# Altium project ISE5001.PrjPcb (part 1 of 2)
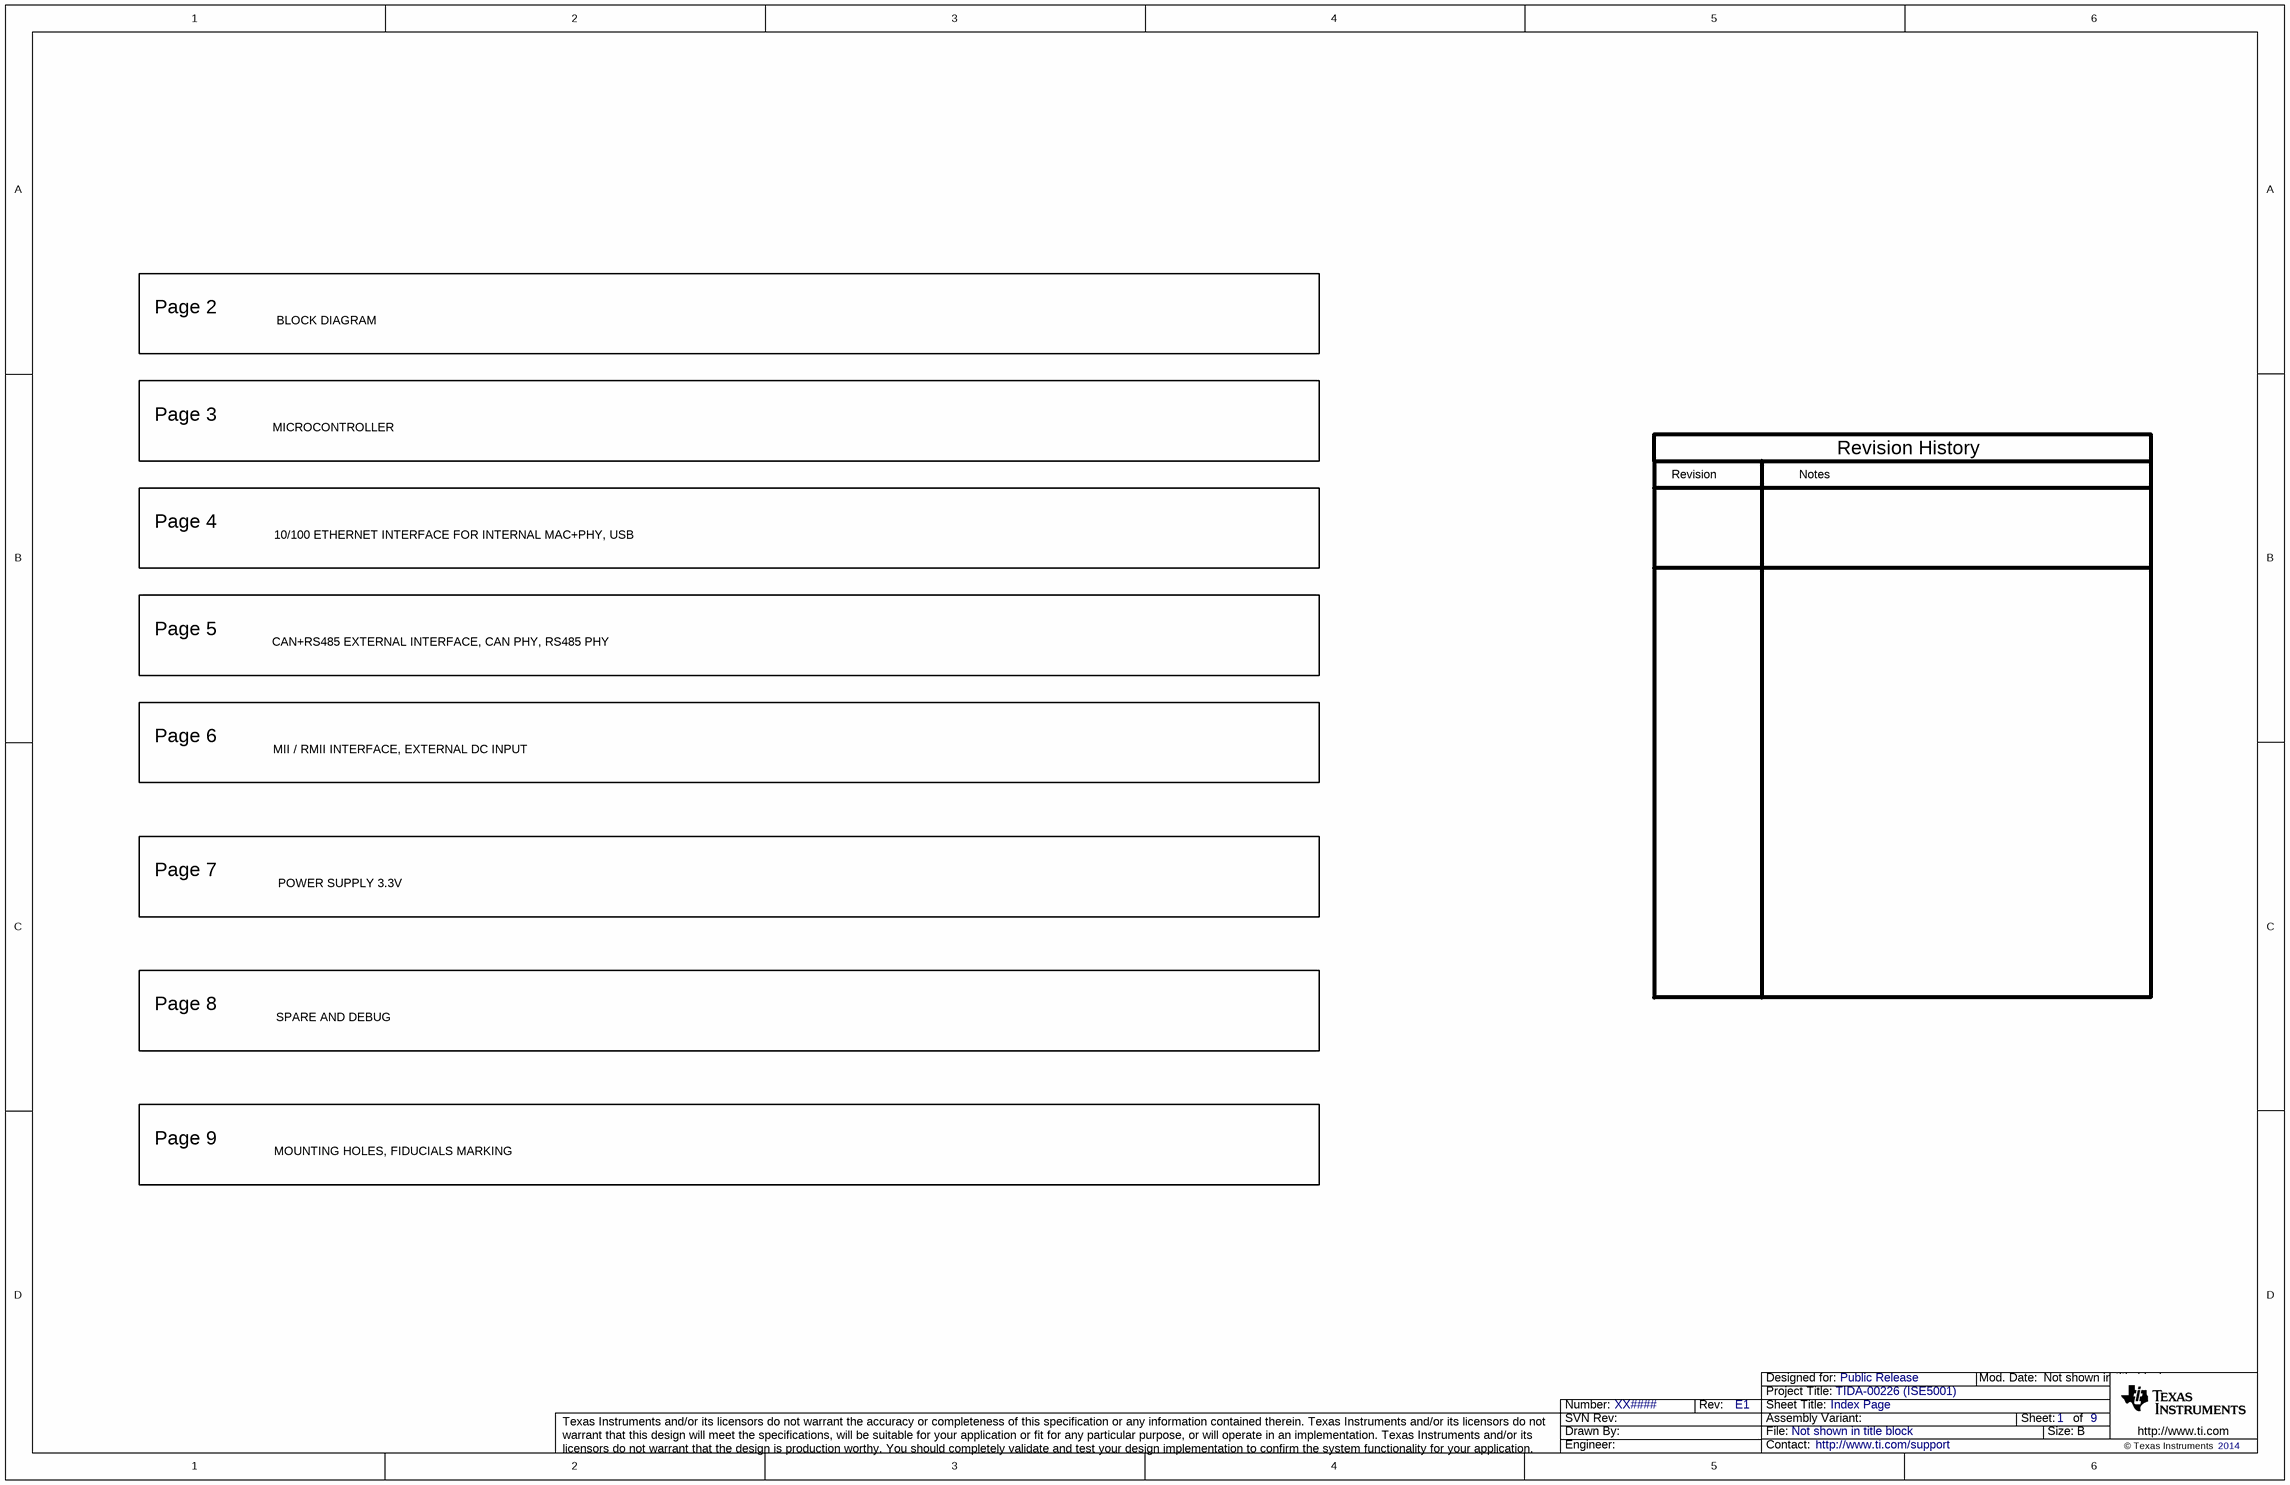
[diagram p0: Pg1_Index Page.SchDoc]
TechSupport: http://www.ti.com/support; SCH_Rev: E1; PRJ_Title: TIDA-00226 (ISE5001); PRJ_Number: XX####; PRJ_Customer: Public Release; CopyrightYear: 2014
9 sheets, 189 parts. Net scope: flat (ports and power ports of the same name join across sheets).
Board file: ISE5001.PcbDoc
Sheets:
  Pg1_Index Page.SchDoc
  Pg2_Block_Diagram.SchDoc
  Pg3_MICROCONTROLLER.SchDoc
  Pg4_10_100_ETHERNET_USB.SchDoc
  Pg5_CAN_RS485.SchDoc
  Pg6_MII_RMII_INTERFACE.SchDoc
  Pg7_POWER_SUPPLY.SchDoc
  Pg8_SPARE_AND_DEBUG.SchDoc
  Pg9_Hardware_ANSI-B.SchDoc

## Sheet Pg1_Index Page.SchDoc: Index Page
size 431 x 279 mm; Date: Not shown in title block; ApprovedBy: Not shown in title block; CheckedBy: Not shown in title block; Author: Not shown in title block; CompanyName: Not shown in title block; Engineer: Not shown in title block; Organization: Not shown in title block; Address1: Not shown in title block; Address2: Not shown in title block; Address3: Not shown in title block; Address4: Not shown in title block; DocumentNumber: 1; Revision: Use project parameter SCH_Rev; SheetNumber: 1; SheetTotal: 9; PageSetup: Record=PageOptions|CenterHorizontal=True|CenterVertical=True|PrintScale=1.00|XCorrection=1.00|YCorrection=1.00|PrintKind=0|BorderSize=5000000|LeftOffset=0|BottomOffset=0|Orientation=2|PaperLength=1000|PaperWidth=1000|Scale=100|PaperSource=15|PrintQuality=600|MediaType=1|DitherType=10|PaperKind=Letter|PrintScaleMode=1

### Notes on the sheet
- Page 2
- BLOCK DIAGRAM
- Page 3
- MICROCONTROLLER
- Revision
- Notes
- Revision History
- Page 4
- 10/100 ETHERNET INTERFACE FOR INTERNAL MAC+PHY, USB
- Page 5
- CAN+RS485 EXTERNAL INTERFACE, CAN PHY, RS485 PHY
- Page 6
- MII / RMII INTERFACE, EXTERNAL DC INPUT
- Page 7
- POWER SUPPLY 3.3V
- Page 8
- SPARE AND DEBUG
- Page 9
- MOUNTING HOLES, FIDUCIALS MARKING

## Sheet Pg2_Block_Diagram.SchDoc: BLOCK DIAGRAM
size 431 x 279 mm; Date: Not shown in title block; ApprovedBy: Not shown in title block; CheckedBy: Not shown in title block; Author: Not shown in title block; CompanyName: Not shown in title block; Engineer: Not shown in title block; Organization: Not shown in title block; Address1: Not shown in title block; Address2: Not shown in title block; Address3: Not shown in title block; Address4: Not shown in title block; DocumentNumber: 2; Revision: Use project parameter SCH_Rev; SheetNumber: 2; SheetTotal: 9; PageSetup: Record=PageOptions|CenterHorizontal=True|CenterVertical=True|PrintScale=1.00|XCorrection=1.00|YCorrection=1.00|PrintKind=0|BorderSize=5000000|LeftOffset=0|BottomOffset=0|Orientation=2|PaperLength=1000|PaperWidth=1000|Scale=100|PaperSource=15|PrintQuality=600|MediaType=1|DitherType=10|PaperKind=Letter|PrintScaleMode=1
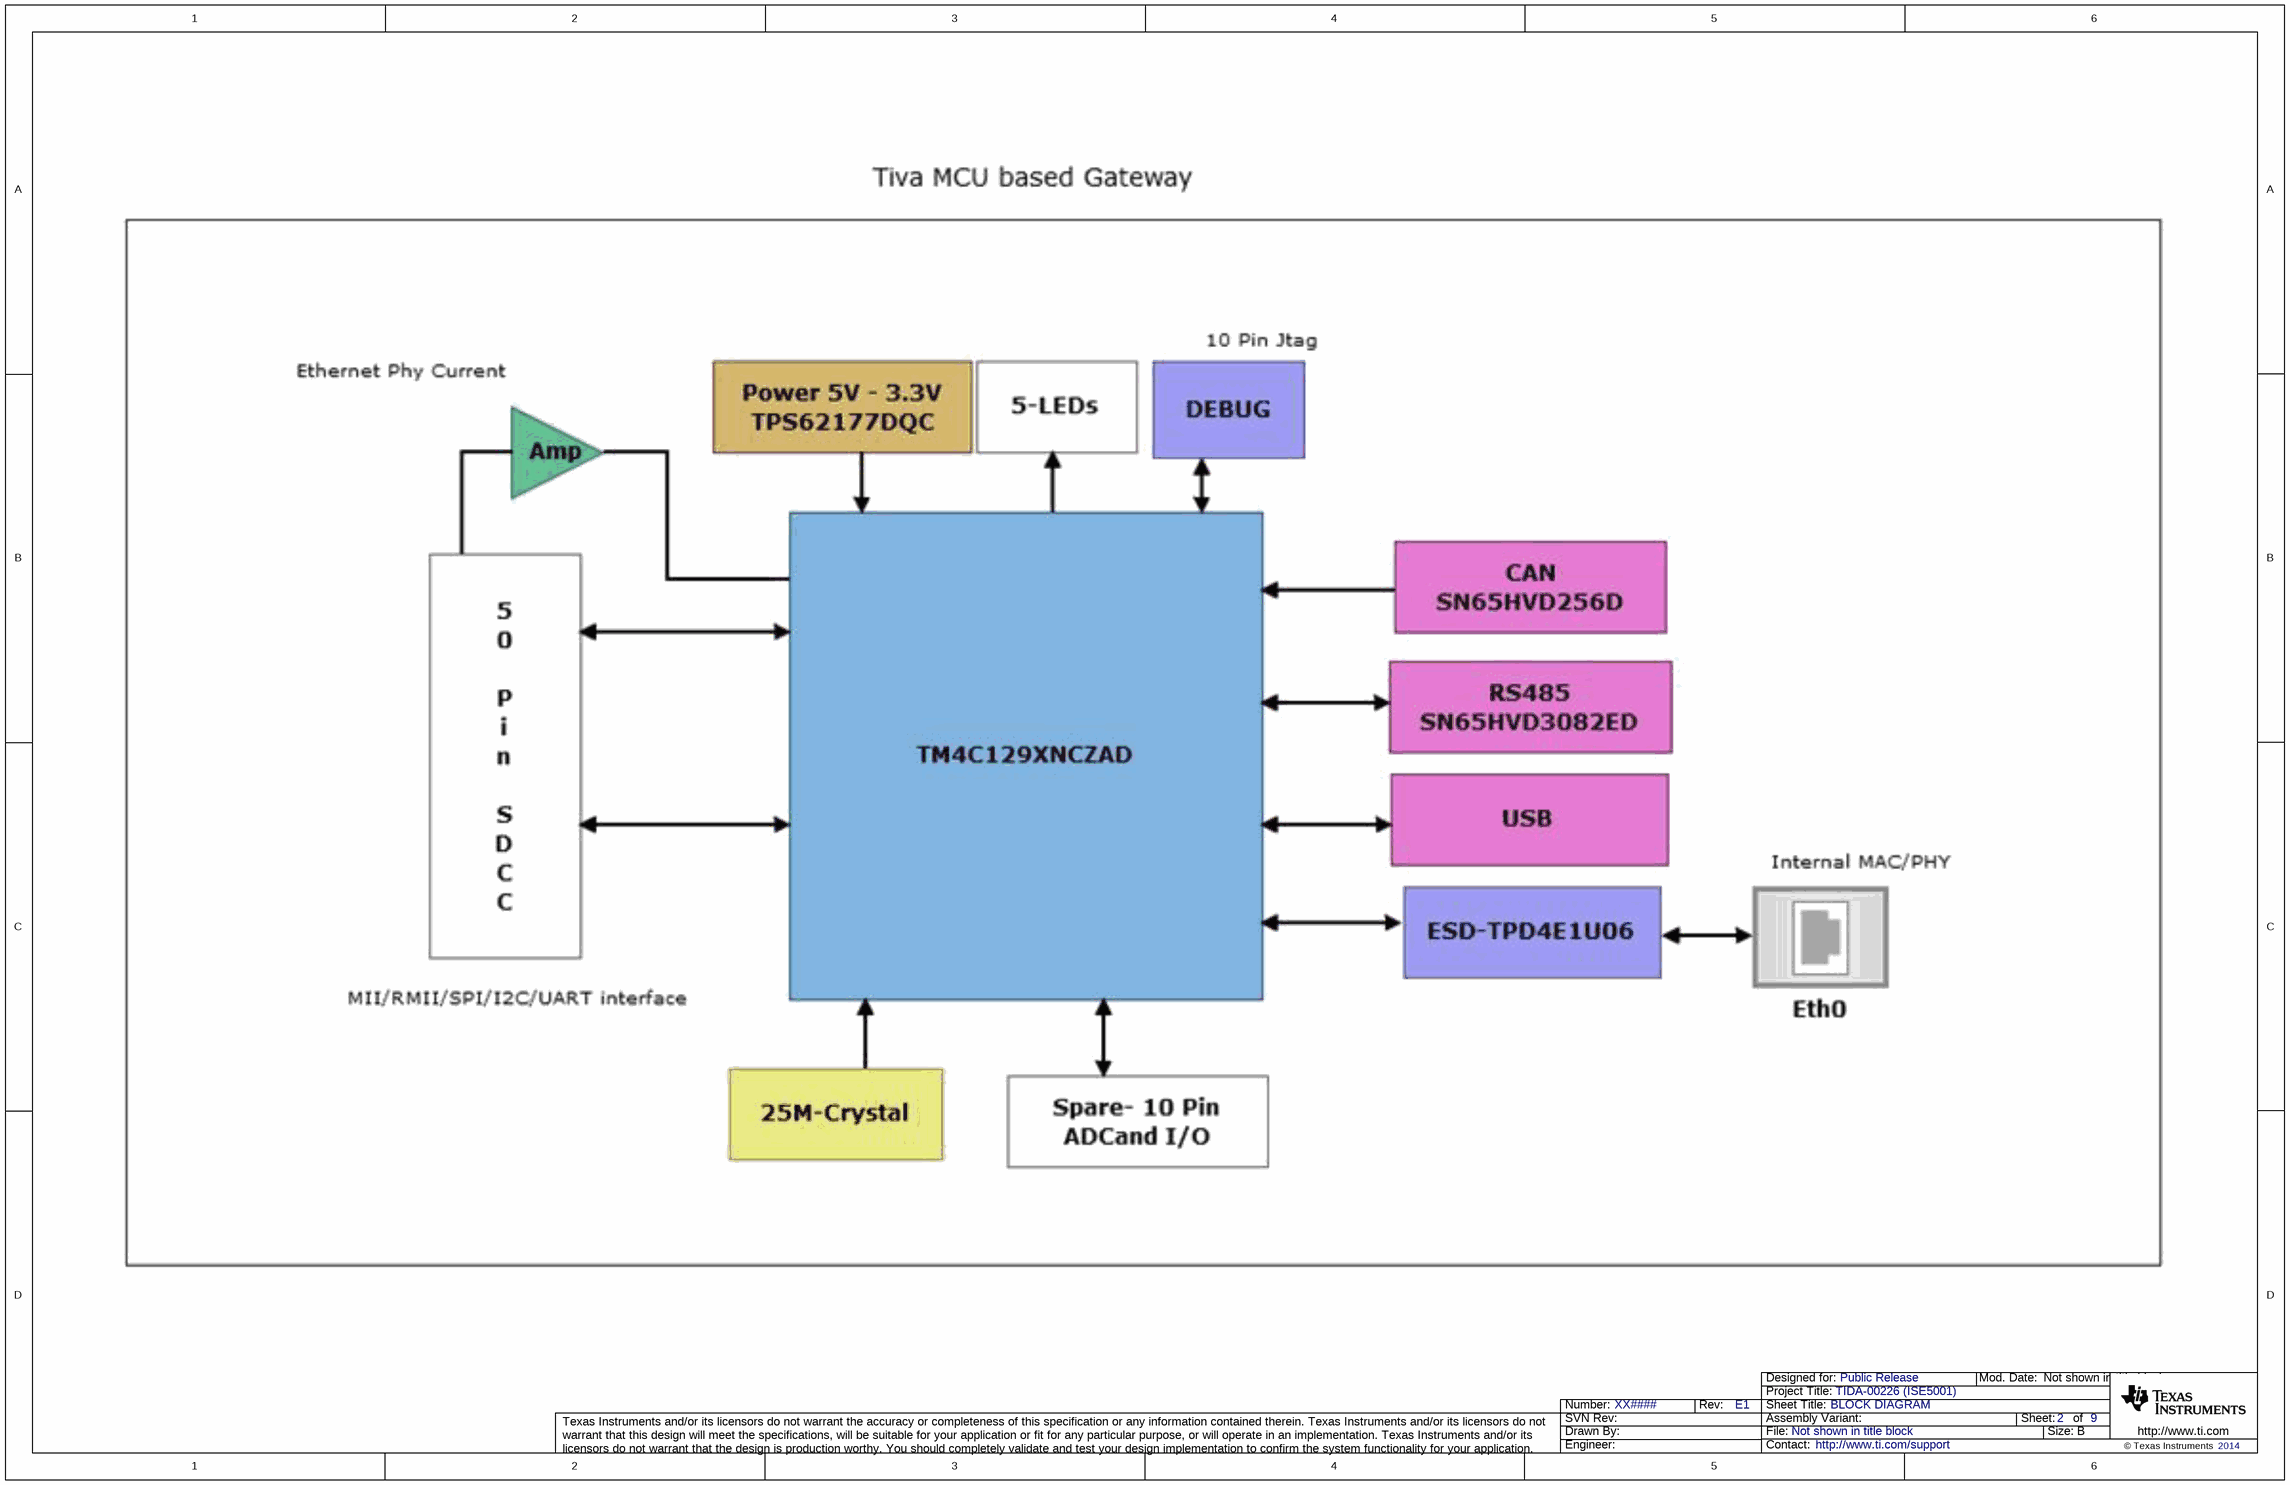
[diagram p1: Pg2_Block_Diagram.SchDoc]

## Sheet Pg3_MICROCONTROLLER.SchDoc: MICROCONTROLLER
size 431 x 279 mm; Date: Not shown in title block; ApprovedBy: Not shown in title block; CheckedBy: Not shown in title block; Author: Not shown in title block; CompanyName: Not shown in title block; Engineer: Not shown in title block; Organization: Not shown in title block; Address1: Not shown in title block; Address2: Not shown in title block; Address3: Not shown in title block; Address4: Not shown in title block; DocumentNumber: 3; Revision: Use project parameter SCH_Rev; SheetNumber: 3; SheetTotal: 9; PageSetup: Record=PageOptions|CenterHorizontal=True|CenterVertical=True|PrintScale=1.00|XCorrection=1.00|YCorrection=1.00|PrintKind=0|BorderSize=5000000|LeftOffset=0|BottomOffset=0|Orientation=2|PaperLength=1000|PaperWidth=1000|Scale=100|PaperSource=15|PrintQuality=600|MediaType=1|DitherType=10|PaperKind=Letter|PrintScaleMode=1
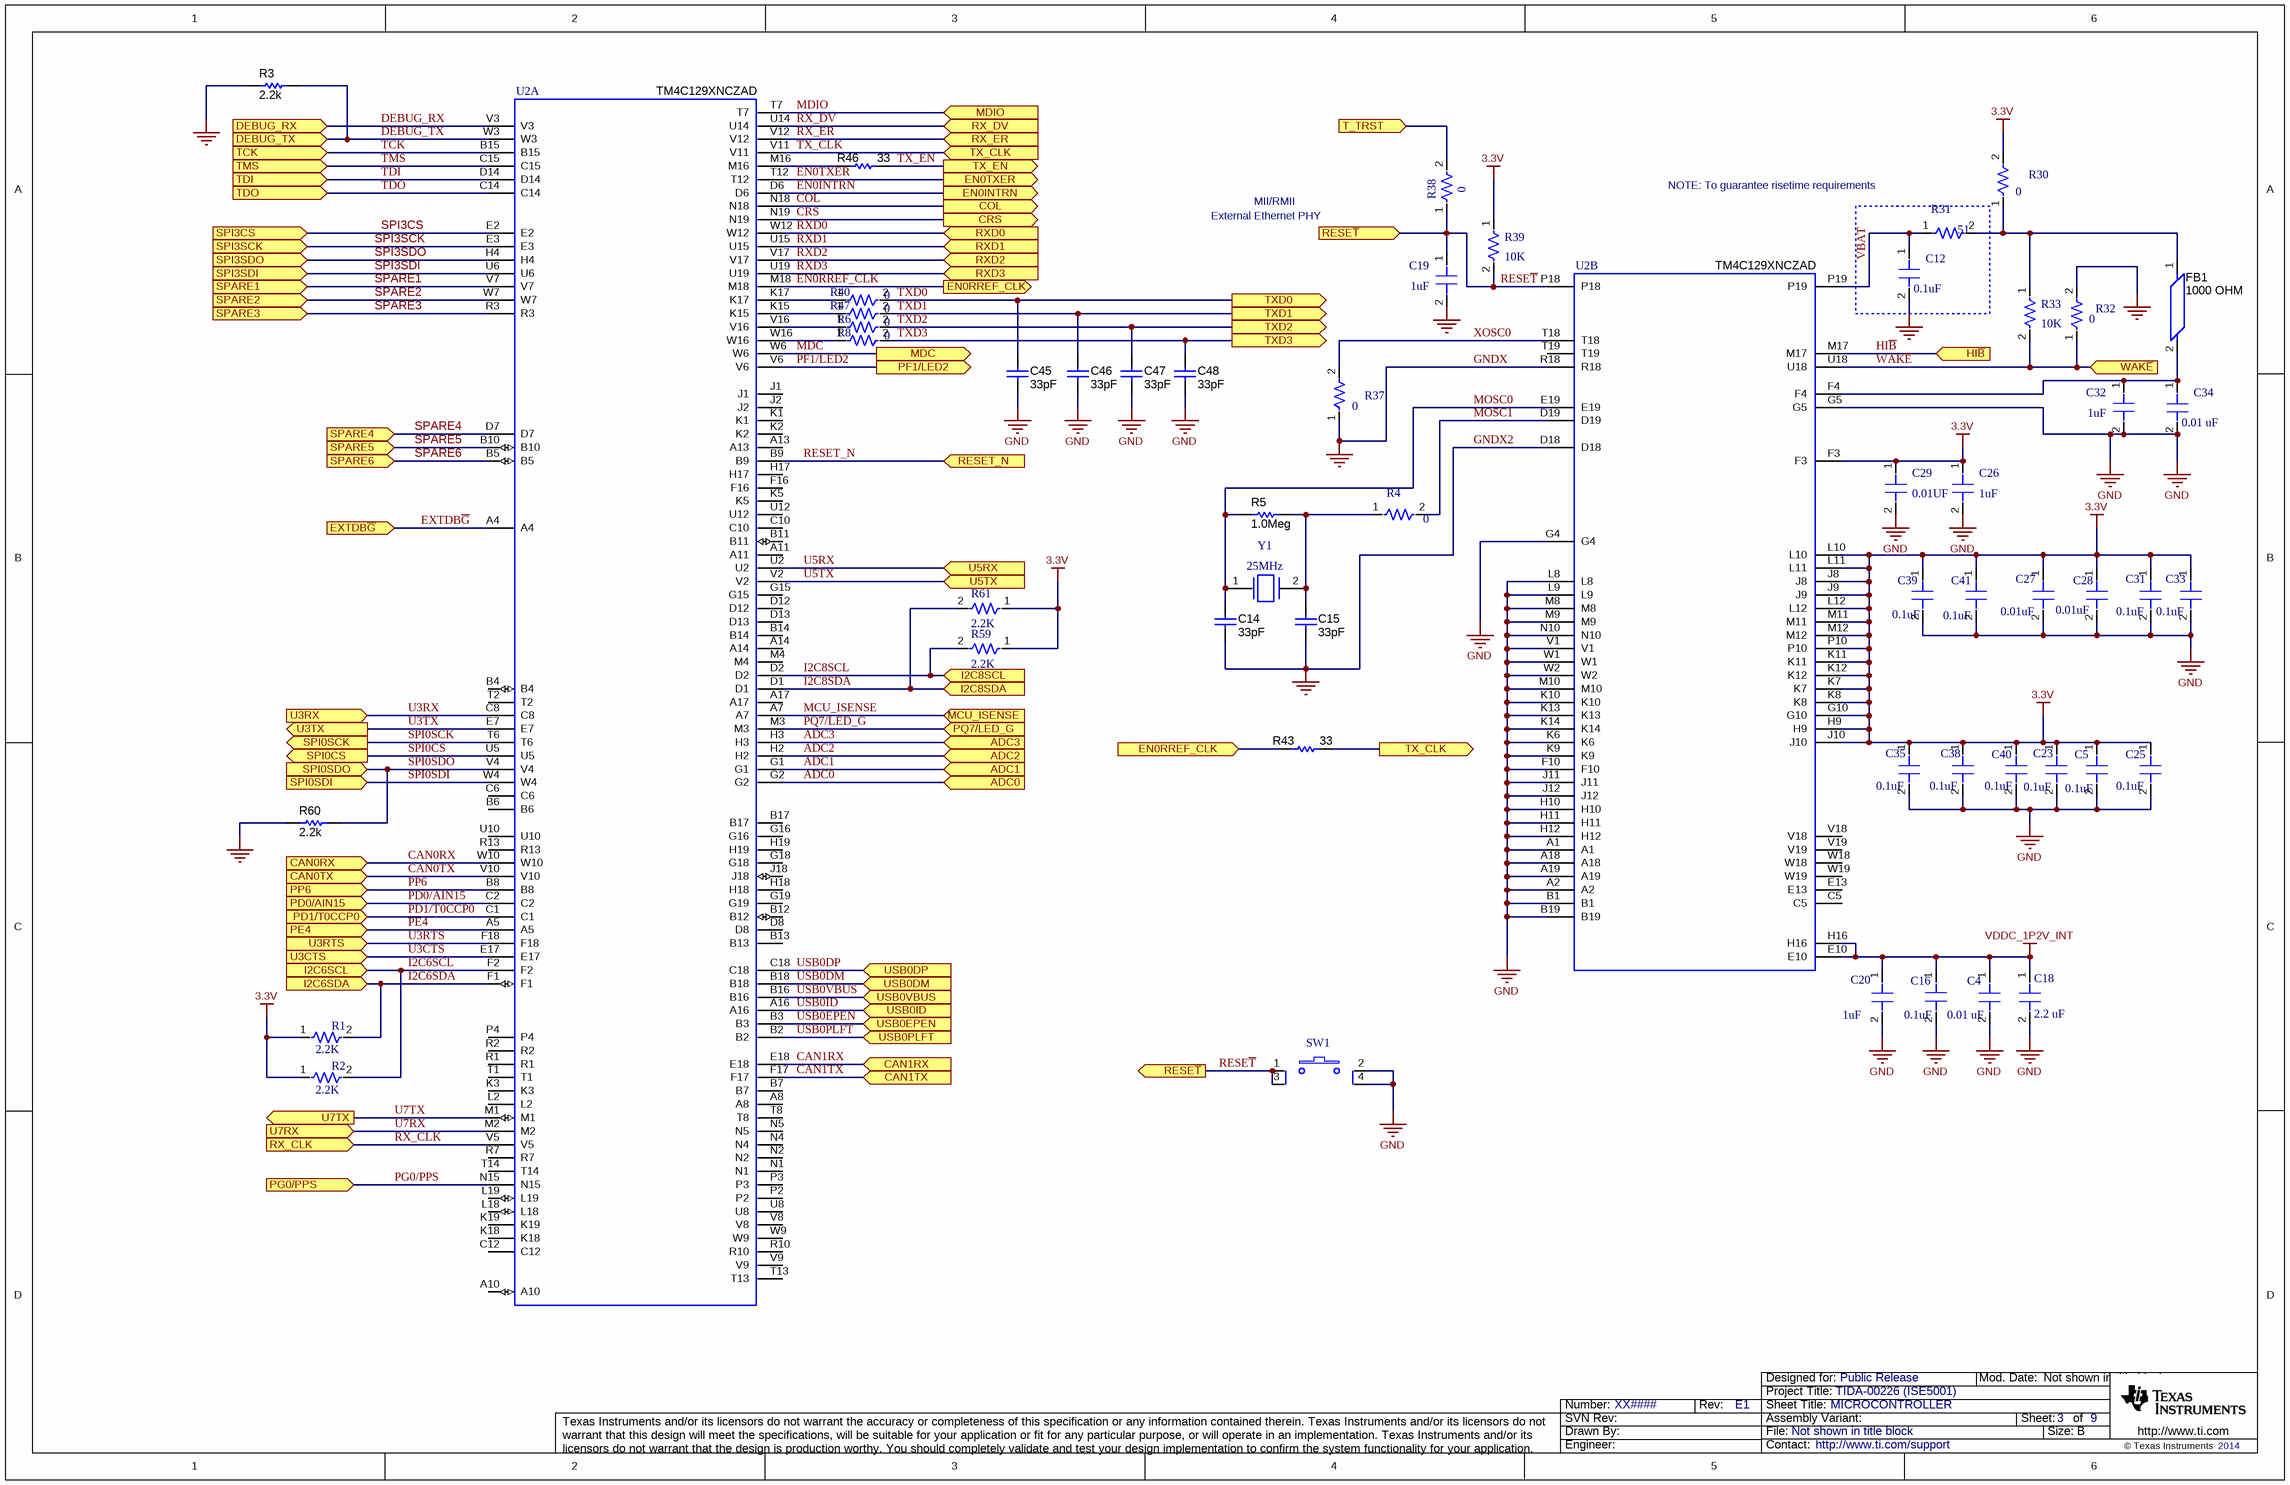
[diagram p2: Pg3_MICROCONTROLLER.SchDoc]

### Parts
C4  value 0.01 uF  [0402]  (hidden comment: CAPC0603)
C5  value 0.1uF  [0603]  (hidden comment: CAPC0603)
C12  value 0.1uF  [0603]  (hidden comment: CAPC0603)
C14  ValueDisplayed: 33pF  [0402]  (hidden comment: GRM1555C1H330JA01D)
C15  ValueDisplayed: 33pF  [0402]  (hidden comment: GRM1555C1H330JA01D)
C16  value 0.1uF  [0603]  (hidden comment: CAPC0603)
C18  value 2.2 uF  [0603]  (hidden comment: CAPC0603)
C19  value 1uF  [0402]  (hidden comment: CAPC0402)
C20  value 1uF  [0402]  (hidden comment: CAPC0402)
C23  value 0.1uF  [0603]  (hidden comment: CAPC0603)
C25  value 0.1uF  [0603]  (hidden comment: CAPC0603)
C26  value 1uF  [0402]  (hidden comment: CAPC0402)
C27  value 0.01uF  [0402]  (hidden comment: CAPC0603)
C28  value 0.01uF  [0402]  (hidden comment: CAPC0603)
C29  value 0.01UF  [0402]  (hidden comment: CAPC0402)
C31  value 0.1uF  [0402]  (hidden comment: CAPC0402)
C32  value 1uF  [0402]  (hidden comment: CAPC0402)
C33  value 0.1uF  [0402]  (hidden comment: CAPC0402)
C34  value 0.01 uF  [0402]  (hidden comment: CAPC0402)
C35  value 0.1uF  [0603]  (hidden comment: CAPC0603)
C38  value 0.1uF  [0603]  (hidden comment: CAPC0603)
C39  value 0.1uF  [0603]  (hidden comment: CAPC0603)
C40  value 0.1uF  [0603]  (hidden comment: CAPC0603)
C41  value 0.1uF  [0603]  (hidden comment: CAPC0603)
C45  ValueDisplayed: 33pF  [0402]  (hidden comment: GRM1555C1H330JA01D)
C46  ValueDisplayed: 33pF  [0402]  (hidden comment: GRM1555C1H330JA01D)
C47  ValueDisplayed: 33pF  [0402]  (hidden comment: GRM1555C1H330JA01D)
C48  ValueDisplayed: 33pF  [0402]  (hidden comment: GRM1555C1H330JA01D)
FB1  1000 OHM  [0603L]
R1  value 2.2K  [0603]  (hidden comment: RESC0603)
R2  value 2.2K  [0603]  (hidden comment: RESC0603)
R3  value 2.2k  [0402]  (hidden comment: CRCW04022K20JNED)
R4  value 0  [0402]  (hidden comment: RESC0402)
R5  value 1.0Meg  [0402]  (hidden comment: CRCW04021M00JNED)
R6  value 0  [0402]  (hidden comment: RESC0402)
R8  value 0  [0402]  (hidden comment: RESC0402)
R30  value 0  [0402]  (hidden comment: RESC0402)
R31  value 51  [0402]  (hidden comment: RESC0402)
R32  value 0  [0402]  (hidden comment: RESC0402)
R33  value 10K  [0402]  (hidden comment: RESC0402)
R37  value 0  [0402]  (hidden comment: RESC0402)
R38  value 0  [0402]  (hidden comment: RESC0402)
R39  value 10K  [0402]  (hidden comment: RESC0402)
R40  value 0  [0402]  (hidden comment: RESC0402)
R43  value 33  [0402]  (hidden comment: CRCW040233R0JNED)
R46  value 33  [0402]  (hidden comment: CRCW040233R0JNED)
R47  value 0  [0402]  (hidden comment: RESC0402)
R59  value 2.2K  [0603]  (hidden comment: RESC0603)
R60  value 2.2k  [0402]  (hidden comment: CRCW04022K20JNED)
R61  value 2.2K  [0603]  (hidden comment: RESC0603)
SW1  SW-EVQQ2  [SW-EVQQ2]  (value not drawn)
U2  Part Number: TM4C129XNCZAD  [BGA212C50P19X19_1000X1000X100]  (hidden comment: TM4C129X)  (parts A,B of 3)
Y1  value 25MHz  [XTAL-NX5032GA]  (hidden comment: XTAL-NX5032GA)

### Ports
ADC0, ADC1, ADC2, ADC3, CAN0RX, CAN0TX, CAN1RX, CAN1TX, COL, CRS, DEBUG_RX, DEBUG_TX, EN0INTRN, EN0RREF_CLK, EN0TXER, EXTDB~{G}, HI~{B}, I2C6SCL, I2C6SDA, I2C8SCL, I2C8SDA, MCU_ISENSE, MDC, MDIO, PD0/AIN15, PD1/T0CCP0, PE4, PF1/LED2, PG0/PPS, PP6, PQ7/LED_G, RESET_N, RESE~{T}, RX_CLK, RX_DV, RX_ER, RXD0, RXD1, RXD2, RXD3, SPARE1, SPARE2, SPARE3, SPARE4, SPARE5, SPARE6 (in), SPI0CS, SPI0SCK (out), SPI0SDI, SPI0SDO, SPI3CS, SPI3SCK, SPI3SDI, SPI3SDO, T_TRST, TCK, TDI, TDO, TMS, TX_CLK, TX_EN, TXD0, TXD1, TXD2, TXD3, U3CTS, U3RTS, U3RX, U3TX (out), U5RX, U5TX, U7RX, U7TX, USB0DM, USB0DP, USB0EPEN, USB0ID, USB0PLFT, USB0VBUS, WAK~{E}

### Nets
3.3V: C5.1 C23.1 C25.1 C26.1 C27.1 C28.1 C29.1 C31.1 C33.1 C35.1 C38.1 C39.1 C40.1 C41.1 R1.1 R2.1 R30.2 R39.1 R59.1 R61.1 U2.F3 U2.G10 U2.H9 U2.J8 U2.J9 U2.J10 U2.K7 U2.K8 U2.K11 U2.K12 U2.L10 U2.L11 U2.L12 U2.M11 U2.M12 U2.P10
GNDX: C4.2 C5.2 C12.2 C14.1 C15.2 C16.2 C18.2 C19.2 C20.2 C23.2 C25.2 C26.2 C27.2 C28.2 C29.2 C31.2 C32.2 C33.2 C34.2 C35.2 C38.2 C39.2 C40.2 C41.2 C45.1 C46.1 C47.1 C48.1 R3.1 R32.2 R37.1 R60.1 SW1.2 SW1.4 U2.A1 U2.A2 U2.A18 U2.A19 U2.B1 U2.B19 U2.D18 U2.F10 U2.G4 U2.G5 U2.H10 U2.H11 U2.H12 U2.J11 U2.J12 U2.K6 U2.K9 U2.K10 U2.K13 U2.K14 U2.L8 U2.L9 U2.M8 U2.M9 U2.M10 U2.N10 U2.R18 U2.V1 U2.W1 U2.W2  [also labelled GND, GNDX2]
VDDC_1P2V_INT: C4.1 C16.1 C18.1 C20.1 U2.E10 U2.H16
EXTDB~{G}: U2.A4 ; port EXTDB~{G}
HI~{B}: U2.M17 ; port HI~{B}
RESE~{T}: C19.1 R38.1 R39.2 SW1.1 SW1.3 U2.P18 ; port RESE~{T}
WAK~{E}: R32.1 R33.2 U2.U18 ; port WAK~{E}
ADC0: U2.G2 ; port ADC0
ADC1: U2.G1 ; port ADC1
ADC2: U2.H2 ; port ADC2
ADC3: U2.H3 ; port ADC3
CAN0RX: U2.W10 ; port CAN0RX
CAN0TX: U2.V10 ; port CAN0TX
CAN1RX: U2.E18 ; port CAN1RX
CAN1TX: U2.F17 ; port CAN1TX
COL: U2.N18 ; port COL
CRS: U2.N19 ; port CRS
DEBUG_RX: U2.V3 ; port DEBUG_RX
DEBUG_TX: R3.2 U2.W3 ; port DEBUG_TX
EN0INTRN: U2.D6 ; port EN0INTRN
EN0RREF_CLK: R43.1 U2.M18 ; port EN0RREF_CLK
EN0TXER: U2.T12 ; port EN0TXER
I2C6SCL: R2.2 U2.F2 ; port I2C6SCL
I2C6SDA: R1.2 U2.F1 ; port I2C6SDA
I2C8SCL: R59.2 U2.D2 ; port I2C8SCL
I2C8SDA: R61.2 U2.D1 ; port I2C8SDA
MCU_ISENSE: U2.A7 ; port MCU_ISENSE
MDC: U2.W6 ; port MDC
MDIO: U2.T7 ; port MDIO
MOSC0: C14.2 R5.1 U2.E19 Y1.1
MOSC1: R4.2 U2.D19
PD0/AIN15: U2.C2 ; port PD0/AIN15
PD1/T0CCP0: U2.C1 ; port PD1/T0CCP0
PE4: U2.A5 ; port PE4
PF1/LED2: U2.V6 ; port PF1/LED2
PG0/PPS: U2.N15 ; port PG0/PPS
PP6: U2.B8 ; port PP6
PQ7/LED_G: U2.M3 ; port PQ7/LED_G
RESET_N: U2.B9 ; port RESET_N
RX_CLK: U2.V5 ; port RX_CLK
RX_DV: U2.U14 ; port RX_DV
RX_ER: U2.V12 ; port RX_ER
RXD0: U2.W12 ; port RXD0
RXD1: U2.U15 ; port RXD1
RXD2: U2.V17 ; port RXD2
RXD3: U2.U19 ; port RXD3
SPARE1: U2.V7 ; port SPARE1
SPARE2: U2.W7 ; port SPARE2
SPARE3: U2.R3 ; port SPARE3
SPARE4: U2.D7 ; port SPARE4
SPARE5: U2.B10 ; port SPARE5
SPARE6: U2.B5 ; port SPARE6
SPI0CS: U2.U5 ; port SPI0CS
SPI0SCK: U2.T6 ; port SPI0SCK
SPI0SDI: U2.W4 ; port SPI0SDI
SPI0SDO: R60.2 U2.V4 ; port SPI0SDO
SPI3CS: U2.E2 ; port SPI3CS
SPI3SCK: U2.E3 ; port SPI3SCK
SPI3SDI: U2.U6 ; port SPI3SDI
SPI3SDO: U2.H4 ; port SPI3SDO
T_TRST: R38.2 ; port T_TRST
TCK: U2.B15 ; port TCK
TDI: U2.D14 ; port TDI
TDO: U2.C14 ; port TDO
TMS: U2.C15 ; port TMS
TX_CLK: R43.2 U2.V11 ; port TX_CLK
TX_EN: R46.2 ; port TX_EN
TXD0: C45.2 R40.2 ; port TXD0
TXD1: C46.2 R47.2 ; port TXD1
TXD2: C47.2 R6.2 ; port TXD2
TXD3: C48.2 R8.2 ; port TXD3
U3CTS: U2.E17 ; port U3CTS
U3RTS: U2.F18 ; port U3RTS
U3RX: U2.C8 ; port U3RX
U3TX: U2.E7 ; port U3TX
U5RX: U2.U2 ; port U5RX
U5TX: U2.V2 ; port U5TX
U7RX: U2.M2 ; port U7RX
U7TX: U2.M1 ; port U7TX
USB0DM: U2.B18 ; port USB0DM
USB0DP: U2.C18 ; port USB0DP
USB0EPEN: U2.B3 ; port USB0EPEN
USB0ID: U2.A16 ; port USB0ID
USB0PLFT: U2.B2 ; port USB0PLFT
USB0VBUS: U2.B16 ; port USB0VBUS
VBAT: C12.1 R31.1 U2.P19
XOSC0: R37.2 U2.T18
NetC15_1: C15.1 R4.1 R5.2 Y1.2
NetC32_1: C32.1 C34.1 FB1.2 U2.F4
NetFB1_1: FB1.1 R30.1 R31.2 R33.1
NetR6_1: R6.1 U2.V16
NetR8_1: R8.1 U2.W16
NetR40_1: R40.1 U2.K17
NetR46_1: R46.1 U2.M16
NetR47_1: R47.1 U2.K15

Not connected (* = marked no-connect by the designer): U2 A8 A10 A11 A13 A14 A17 B4 B6 B7 B11 B12 B13 B14 B17 C5 C6 C10 C12 D8 D12 D13 E13 F16 G15 G16 G18 G19 H17 H18 H19 J1 J2 J18 K1 K2 K3 K5 K18 K19 L2 L18 L19 M4 N1 N2 N4 N5 P2 P3 P4 R1 R2 R7 R10 R13 T1 T2 T8 T13 T14 T19 U8 U10 U12 V8 V9 V18 V19 W9 W18 W19

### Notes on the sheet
- External Ethernet PHY
- MII/RMII
- NOTE: To guarantee risetime requirements

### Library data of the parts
C4 = CAPC0603: Capacitor, 0.01uF 25V, 10% 0402 X7R; Part Number: TMK105B7103KV-F; PCB DECAL: CAPC0402N; GNUM: G10-C0402-C103-BBA
C5 C12 C23 C25 C35 C38-C41 = CAPC0603: Capacitor, 0.1uF 50V, 20% 0603 X7R; Part Number: C1608X7R1H104M; GNUM: G10-C0603-C104-ACA; PCB DECAL: CAPC0603L
C14 C15 C45-C48 = GRM1555C1H330JA01D: CAP, CERM, 33pF, 50V, +/-5%, C0G/NP0, 0402; Manufacturer: MuRata; Polarized: N; CompType: Capacitor; U/M: EA; Cap_F: 0.000000000033; Tolerance_%: 5; Value1: Unknown; VDC_V: 50; TaMin_C: -55; TaMax_C: 125
C16 = CAPC0603: Capacitor, 0.1uF 50V, 20% 0603 X7R; Part Number: C1608X7R1H104M; PCB DECAL: CAPC0603L; GNUM: G10-C0603-C104-ACA
C18 = CAPC0603: Capacitor, 2.2uF, 16V, 10%, 0603, X5R; Part Number: GRM188R61C225KE15D; PCB DECAL: CAPC0603L; GNUM: G10-C0603-C225-HBB
C19 C20 C26 C32 = CAPC0402: Capacitor, 1uF , X5R, 10V, 0402; Part Number: C1005X5R1A105M050BB; PCB DECAL: CAPC0402N; GNUM: G10-C0402-C105-GCB
C27 C28 = CAPC0603: Capacitor, 0.01uF 25V, 10% 0402 X7R; Part Number: TMK105B7103KV-F; PCB DECAL: CAPC0402L; GNUM: G10-C0402-C103-BBA
C29 C31 C33 = CAPC0402: Capacitor, 0.1uF 16V, 10% 0402 X7R; Part Number: EMK105B7104KV-F; PCB DECAL: CAPC0402N; GNUM: G10-C0402-C104-HBA
C34 = CAPC0402: Capacitor, 0.01uF 25V, 10% 0402 X7R; Part Number: TMK105B7103KV-F; PCB DECAL: CAPC0402N; GNUM: G10-C0402-C103-BBA
FB1 = MMZ1608B102C: FERRITE CHIP 1000 OHM 300MA 0603; Manufacturer: TDK Corporation; CompType: Ferrite Bead
R1 R2 R59 R61 = RESC0603: Resistor, 2.2K OHM 1/10W 5% 0603 SMD; Manufacturer #1: Generic; Part Number: CRCW06032K20JNEA; PCB DECAL: RESC0603N; GNUM: G11-R0603-R222-AAA; Description: Resistor,Chip;1.60mm L X 0.83mm W X 0.60mm H; Geometry.Height: 0.6mm; PCBL.Component: CHP;RESC;1500;1700;150;400;700;950;600; PCBL.Process: F;N;50;50;200;100;200;250;350;-50;0
R3 R60 = CRCW04022K20JNED: RES, 2.2k ohm, 5%, 0.063W, 0402; Manufacturer: Vishay-Dale; CompType: Resistor; Res_ohm: 2200; Value_Code: 2k20; Tolerance_%: 5; Power_W: 0.063; VDC_V: 50; TempCo: 200 ppm/C; EIA_Code: E24; U/M: EA
R4 R6 R8 R30 R32 R37 R38 R40 R47 = RESC0402: Resistor, 0 ohm, 1/10W, 5%, 0402; Manufacturer #1: Generic; Part Number: ERJ-2GE0R00X; Description: Resistor,Chip;1.00mm L X 0.5mm W X 0.35mm H; Geometry.Height: 0.35mm; PCBL.Component: CHP;RESC;1500;1700;150;400;700;950;600; PCBL.Process: F;N;50;50;200;100;200;250;350;-50;0; PCB DECAL: RESC0402N; GNUM: G11-R0402-0000-AAA
R5 = CRCW04021M00JNED: RES, 1.0Meg ohm, 5%, 0.063W, 0402; Manufacturer: Vishay-Dale; CompType: Resistor; Res_ohm: 1000000; Value_Code: 1M00; Tolerance_%: 5; Power_W: 0.063; VDC_V: 50; TempCo: 200 ppm/C; EIA_Code: E24; U/M: EA
R31 = RESC0402: Resistor, 51 ohm, 1/10W, 5%, 0402; Manufacturer #1: Generic; Part Number: ERJ-2GEJ510X; Description: Resistor,Chip;1.00mm L X 0.5mm W X 0.35mm H; Geometry.Height: 0.35mm; PCBL.Component: CHP;RESC;1500;1700;150;400;700;950;600; PCBL.Process: F;N;50;50;200;100;200;250;350;-50;0; PCB DECAL: RESC0402N; GNUM: G11-R0402-51R0-AAA
R33 R39 = RESC0402: Resistor, 10k ohm, 1/10W, 5%, 0402 Thick Film; Manufacturer #1: Generic; Part Number: RC0402FR-0710KL; Description: Resistor,Chip;1.00mm L X 0.5mm W X 0.35mm H; Geometry.Height: 0.35mm; PCBL.Component: CHP;RESC;1500;1700;150;400;700;950;600; PCBL.Process: F;N;50;50;200;100;200;250;350;-50;0; PCB DECAL: RESC0402N; GNUM: G11-R0402-1002-AAA
R43 R46 = CRCW040233R0JNED: RES, 33 ohm, 5%, 0.063W, 0402; Manufacturer: Vishay-Dale; CompType: Resistor; Value_Code: 33R0; Tolerance_%: 5; Power_W: 0.063; VDC_V: 50; TempCo: 200 ppm/C; EIA_Code: E24; U/M: EA
SW1 = SW-EVQQ2: Switch, Tact 6mm SMT, 160gf; Manufacturer #1: Panasonic; Part Number: B3S-1000; Description: Switch, Tact 6mm SMT, 50gf; GNUM: G21-4P6MM-B3S1-AAA
U2 = TM4C129X: Stellaris MCU TM4C129XNCZAD 212 BGA, super; GNUM: G50-BG212-C129-ALI; PCB DECAL: BGA19X19-05MM-T1; Geometry.Height: 50.00mil
Y1 = XTAL-NX5032GA: Crystal, 25.00MHz 5.0x3.2mm SMT; Part Number: 445I23D25M00000; Description: Crystal, 16.00MHz 5.0x3.2mm SMT; GNUM: G15-5X3P2-2506-AAA

## Sheet Pg4_10_100_ETHERNET_USB.SchDoc: 10/100 ETHERNET USB
size 431 x 279 mm; Date: Not shown in title block; ApprovedBy: Not shown in title block; CheckedBy: Not shown in title block; Author: Not shown in title block; CompanyName: Not shown in title block; Engineer: Not shown in title block; Organization: Not shown in title block; Address1: Not shown in title block; Address2: Not shown in title block; Address3: Not shown in title block; Address4: Not shown in title block; DocumentNumber: 4; Revision: Use project parameter SCH_Rev; SheetNumber: 4; SheetTotal: 9; PageSetup: Record=PageOptions|CenterHorizontal=True|CenterVertical=True|PrintScale=1.00|XCorrection=1.00|YCorrection=1.00|PrintKind=0|BorderSize=5000000|LeftOffset=0|BottomOffset=0|Orientation=2|PaperLength=1000|PaperWidth=1000|Scale=100|PaperSource=15|PrintQuality=600|MediaType=1|DitherType=10|PaperKind=Letter|PrintScaleMode=1
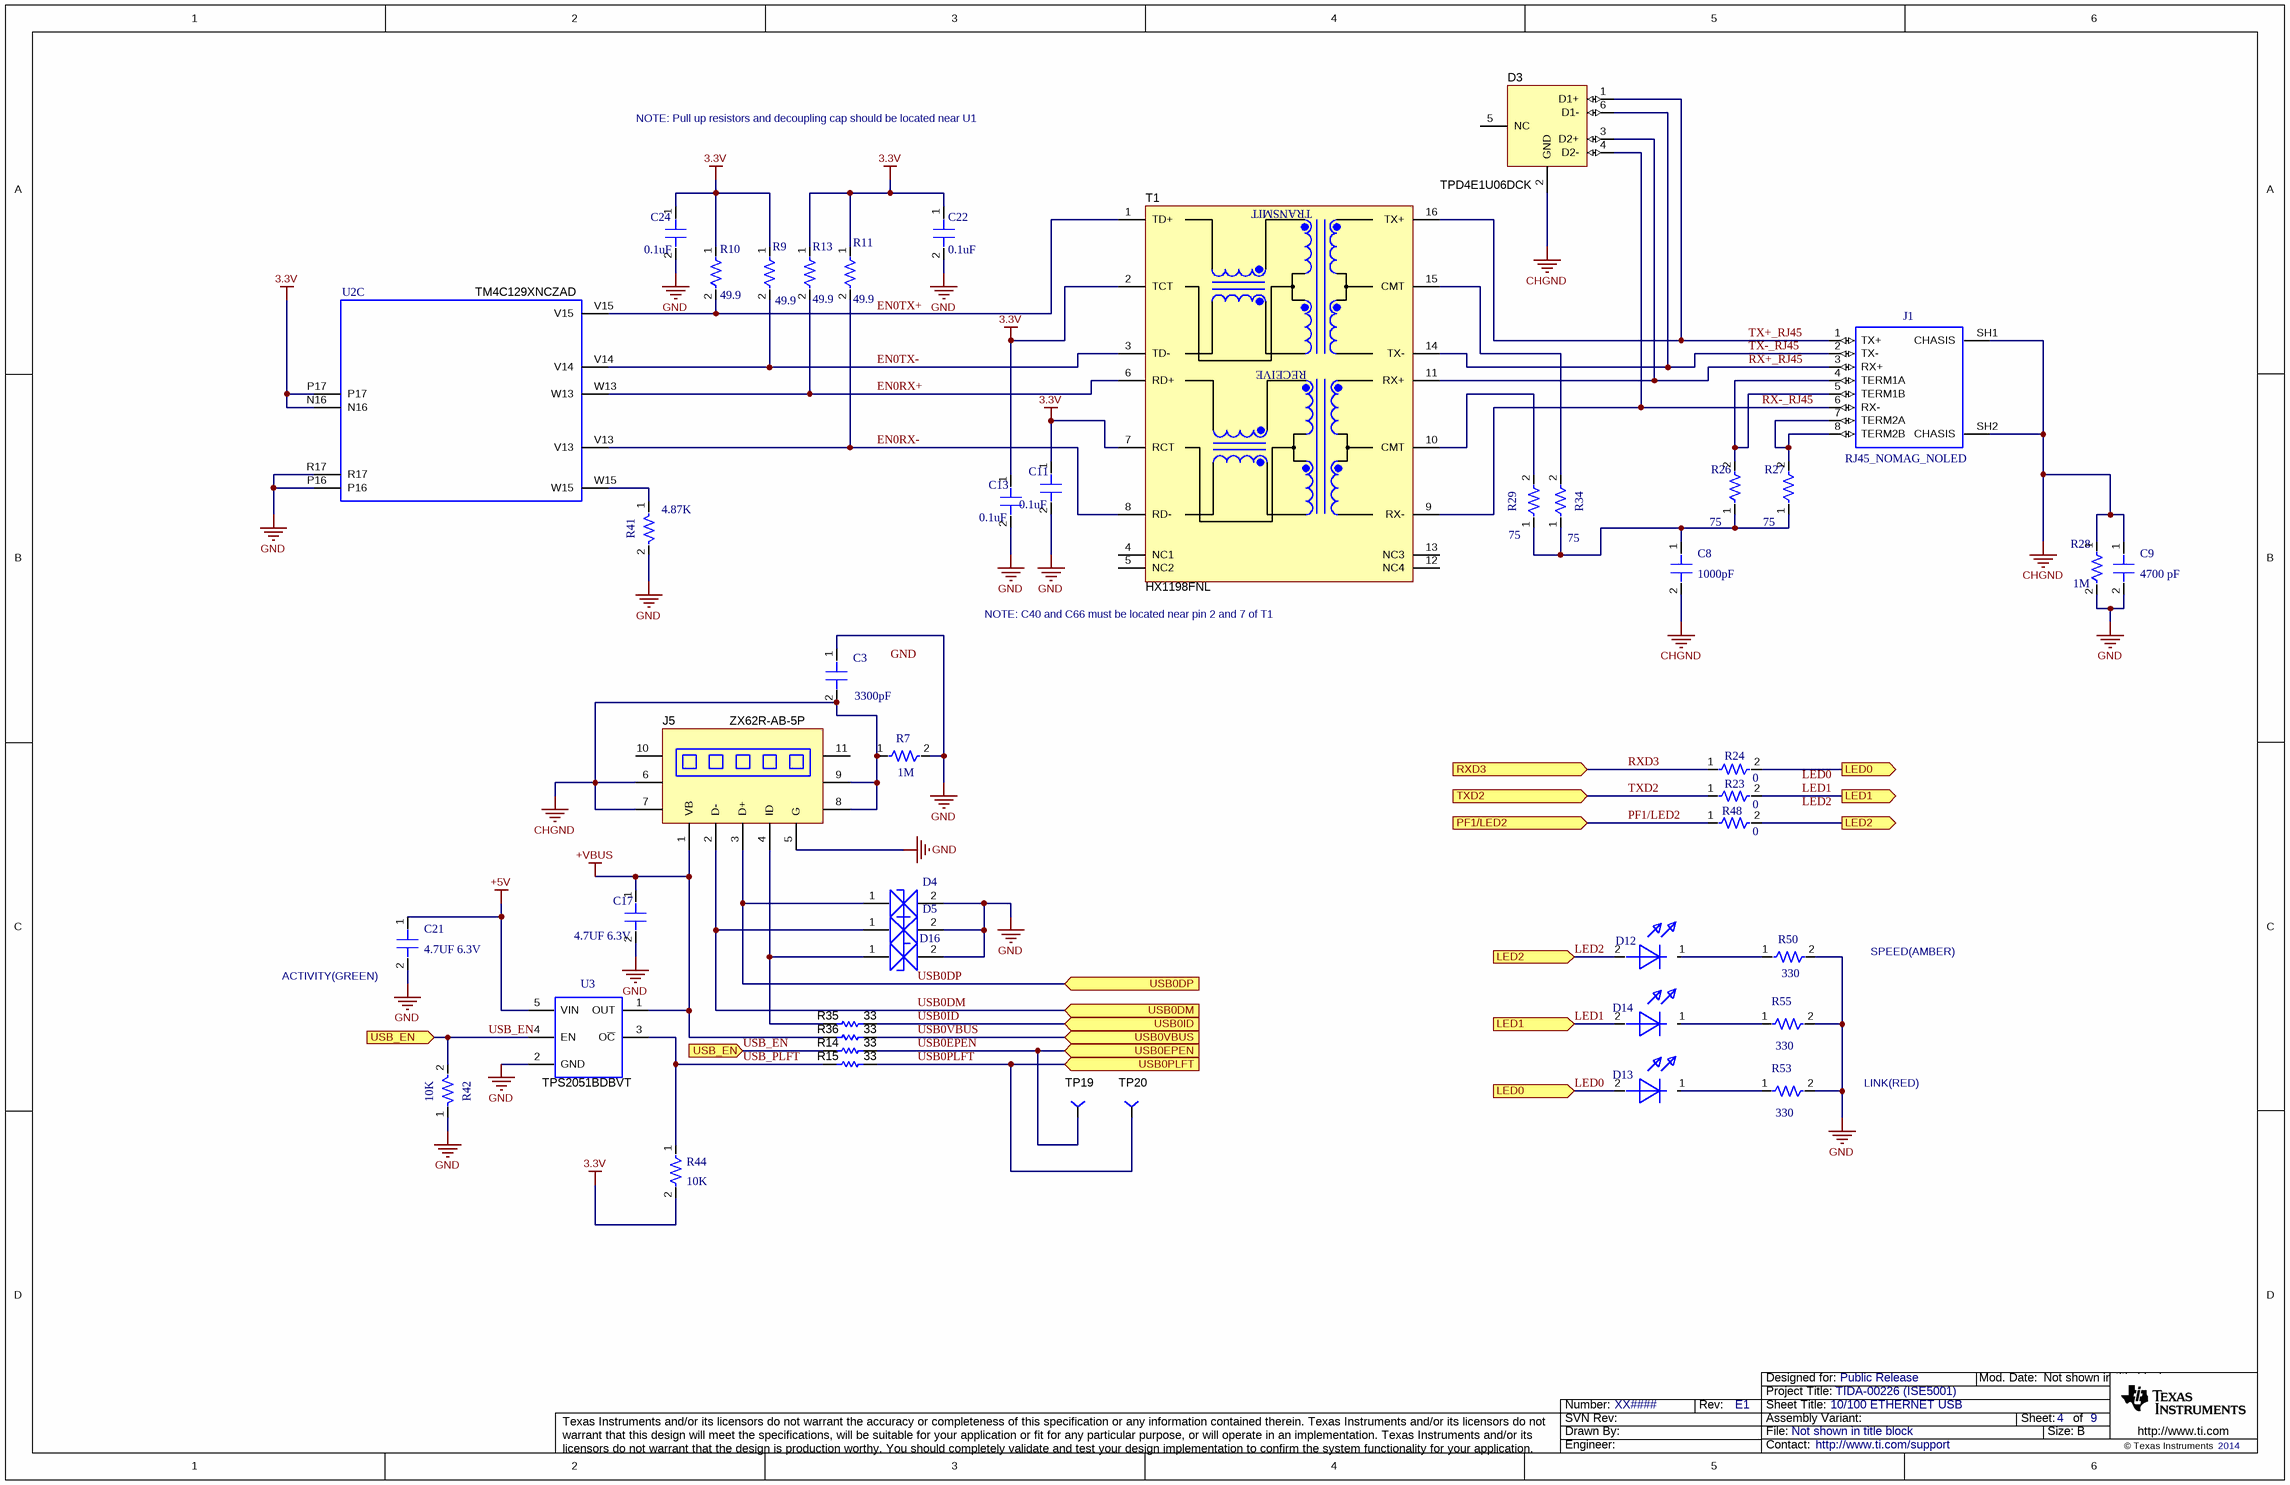
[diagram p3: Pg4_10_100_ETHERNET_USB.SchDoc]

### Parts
C3  value 3300pF  [0603]  (hidden comment: CAPC0603)
C8  value 1000pF  [1210]  (hidden comment: CAPC1210)
C9  value 4700 pF  [1812]  (hidden comment: CAPC0603)
C11  value 0.1uF  [0603]  (hidden comment: CAPC0603)
C13  value 0.1uF  [0603]  (hidden comment: CAPC0603)
C17  value 4.7UF 6.3V  [0805]  (hidden comment: CAPC0805)
C21  value 4.7UF 6.3V  [0805]  (hidden comment: CAPC0805)
C22  value 0.1uF  [0603]  (hidden comment: CAPC0603)
C24  value 0.1uF  [0603]  (hidden comment: CAPC0603)
D3  TPD4E1U06DCK  [DCK0006A_N]
D4  B72590D0050H160  [RESC0402N]  (value not drawn)
D5  B72590D0050H160  [RESC0402N]  (value not drawn)
D12  LED-0805  [DIOC0805N]  (value not drawn)
D13  LED-0805  [DIOC0805N]  (value not drawn)
D14  LED-0805  [DIOC0805N]  (value not drawn)
D16  B72590D0050H160  [RESC0402N]  (value not drawn)
J1  RJ45_NOMAG_NOLED  [TE_6116526-1]
J5  ZX62R-AB-5P  [CON-USB-MICRO-REV]
R7  value 1M  [0603]  (hidden comment: RESC0603)
R9  value 49.9  [0603]  (hidden comment: RESC0603)
R10  value 49.9  [0603]  (hidden comment: RESC0603)
R11  value 49.9  [0603]  (hidden comment: RESC0603)
R13  value 49.9  [0603]  (hidden comment: RESC0603)
R14  value 33  [0402]  (hidden comment: CRCW040233R0JNED)
R15  value 33  [0402]  (hidden comment: CRCW040233R0JNED)
R23  value 0  [0402]  (hidden comment: RESC0402)
R24  value 0  [0402]  (hidden comment: RESC0402)
R26  value 75  [0603]  (hidden comment: RESC0603)
R27  value 75  [0603]  (hidden comment: RESC0603)
R28  value 1M  [1206]  (hidden comment: RESC1206)
R29  value 75  [0603]  (hidden comment: RESC0603)
R34  value 75  [0603]  (hidden comment: RESC0603)
R35  value 33  [0402]  (hidden comment: CRCW040233R0JNED)
R36  value 33  [0402]  (hidden comment: CRCW040233R0JNED)
R41  value 4.87K  [0603]  (hidden comment: RESC0603)
R42  value 10K  [0603]  (hidden comment: RESC0603)
R44  value 10K  [0402]  (hidden comment: RESC0402)
R48  value 0  [0402]  (hidden comment: RESC0402)
R50  value 330  [0603]  (hidden comment: RESC0603)
R53  value 330  [0603]  (hidden comment: RESC0603)
R55  value 330  [0603]  (hidden comment: RESC0603)
T1  HX1198FNL  [XFMR_ HX1198FNL]
TP19  TP1_PD40_D0.5_S50  [TP1_PD40_D0.5_S50]  (value not drawn)
TP20  TP1_PD40_D0.5_S50  [TP1_PD40_D0.5_S50]  (value not drawn)
U2  Part Number: TM4C129XNCZAD  [BGA212C50P19X19_1000X1000X100]  (hidden comment: TM4C129X)  (part C of 3)
U3  Part Number: TPS2051BDBVT  [DBV5]  (hidden comment: TPS2051B)

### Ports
LED0, LED1, LED2, PF1/LED2, RXD3, TXD2, USB0DM, USB0DP, USB0EPEN, USB0ID, USB0PLFT, USB0VBUS, USB_EN

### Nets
3.3V: C11.1 C13.1 C22.1 C24.1 R9.1 R10.1 R11.1 R13.1 R44.2 T1.2(TCT) T1.7(RCT) U2.N16 U2.P17
+5V: C21.1 U3.5(VIN)
+VBUS: C17.1 J5.1(VB) R36.1 U3.1(OUT)
CHGND: C3.2 C8.2 C9.1 D3.2(GND) J1.SH1(CHASIS) J1.SH2(CHASIS) J5.6 J5.7 J5.8 J5.9 R7.1 R28.1
GND: C3.1 C9.2 C11.2 C13.2 C17.2 C21.2 C22.2 C24.2 D4.2 D5.2 D16.2 J5.5(G) R7.2 R28.2 R41.2 R42.1 R50.2 R53.2 R55.2 U2.P16 U2.R17 U3.2(GND)  [project net GNDX]
EN0RX+: R13.2 T1.6(RD+) U2.W13
EN0RX-: R11.2 T1.8(RD-) U2.V13
EN0TX+: R10.2 T1.1(TD+) U2.V15
EN0TX-: R9.2 T1.3(TD-) U2.V14
LED0: D13.2 R24.2 ; port LED0
LED1: D14.2 R23.2 ; port LED1
LED2: D12.2 R48.2 ; port LED2
PF1/LED2: R48.1 ; port PF1/LED2
RX+_RJ45: D3.3(D2+) J1.3(RX+) T1.11(RX+)
RX-_RJ45: D3.4(D2-) J1.6(RX-) T1.9(RX-)
RXD3: R24.1 ; port RXD3
TX+_RJ45: D3.1(D1+) J1.1(TX+) T1.16(TX+)
TX-_RJ45: D3.6(D1-) J1.2(TX-) T1.14(TX-)
TXD2: R23.1 ; port TXD2
USB0DM: D5.1 J5.2(D-) ; port USB0DM
USB0DP: D4.1 J5.3(D+) ; port USB0DP
USB0EPEN: R14.2 TP19.1 ; port USB0EPEN
USB0ID: R35.2 ; port USB0ID
USB0PLFT: R15.2 TP20.1 ; port USB0PLFT
USB0VBUS: R36.2 ; port USB0VBUS
USB_EN: R14.1 R42.2 U3.4(EN) ; port USB_EN
USB_PLFT: R15.1 R44.1 U3.3(O~{C})
NetC8_1: C8.1 R26.1 R27.1 R29.1 R34.1
NetD12_1: D12.1 R50.1
NetD13_1: D13.1 R53.1
NetD14_1: D14.1 R55.1
NetD16_1: D16.1 J5.4(ID) R35.1
NetJ1_4: J1.4(TERM1A) J1.5(TERM1B) R26.2
NetJ1_7: J1.7(TERM2A) J1.8(TERM2B) R27.2
NetR29_2: R29.2 T1.10(CMT)
NetR34_2: R34.2 T1.15(CMT)
NetR41_1: R41.1 U2.W15

Not connected (* = marked no-connect by the designer): D3 5(NC); J5 10 11; T1 4(NC1) 5(NC2) 12(NC4) 13(NC3)

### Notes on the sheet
- NOTE: Pull up resistors and decoupling cap should be located near U1
- (near T1) NOTE: C40 and C66 must be located near pin 2 and 7 of T1
- SPEED(AMBER)
- (near C21) ACTIVITY(GREEN)
- LINK(RED)
- Labels drawn without touching a wire or pin: $$$22985, GND, LED0, LED2

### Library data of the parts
C3 = CAPC0603: Capacitor, 3300pF, 50V, 10%, X7R, 0603; Part Number: C1608X7R1H332K; Sim.Analog.Order: Model$; PCB DECAL: CAPC0603N; GNUM: G10-C0603-C332-ABA
C8 = CAPC1210: CAP CER 1000PF 2KV 20% X7R 1210; Part Number: C1210C102MGRACTU; GNUM: G10-C1210-C102-ZCA
C9 = CAPC0603: Capacitor, 4700pF, 2kV, 10%, X7R, 1812; Part Number: 1812GC472KAT1A; GNUM: G10-C1812-C472-ZBA; PCB DECAL: 1812MIL
C11 C13 C22 C24 = CAPC0603: as C5 on sheet Pg3_MICROCONTROLLER
C17 C21 = CAPC0805: Capacitor, 4.7uF, 6.3V, 10% 0805, X5R; Part Number: JMK212BJ475KG-T; GNUM: G10-C0805-C475-DBB; Geometry.Height: 1.1mm; PCBL.Component: CHP;CAPC;1800;2200;250;750;1050;1450;1100; PCBL.Process: F;N;50;50;200;100;200;250;350;-50;0
D3 = TPD4E1U06DCK: Quad Channel High Speed ESD Protection Device, DCK0006A; Alternate Manufacturer: None; Manufacturer: Texas Instruments; SymbolCreator: a0411947; CompType: IC; U/M: EA
D4 D5 D16 = B72590D0050H160: Diode, 5.6V ESD Suppressor 0402; GNUM: G14-D0402-5V6-DAA
D12 = LED-0805: LED AMBER CLEAR 0805 SMD; Manufacturer #1: LITE-ON; Part Number: LTST-C170AKT; GNUM: G14-D0805-AMB0-AAA; Description: SMT LED IN 0805 PACK
D13 = LED-0805: LED, Red 630nm, Clear 0805 SMD; Manufacturer #1: LITE-ON; Part Number: LTST-C171EKT; Description: SMT LED IN 0805 PACK; GNUM: G14-D0805-RD00-AAA
D14 = LED-0805: LED, Green 565nm, Clear 0805 SMD; Manufacturer #1: LITE-ON; Part Number: LTST-C171GKT; Description: SMT LED IN 0805 PACK; GNUM: G14-D0805-GR00-AAA
J1 = RJ45_NOMAG_NOLED: Connector, RJ45 NO MAG, shielded THRU HOLE; Part Number: 6116526-1; PCB DECAL: 406541; GNUM: G20-8RJ45-ENET-AAA
J5 = ZX62R-AB-5P: Connector, USB micro AB Receptacle Reversed SMD; Manufacturer: HIROSE ELECTRIC CO. LTD.; SymbolCreator: x0199378
R7 = RESC0603: Resistor, 1M OHM 1/10W 5% 0603 SMD; Manufacturer #1: Generic; Part Number: ERJ-3GEYJ105V; Description: Resistor,Chip;1.60mm L X 0.83mm W X 0.60mm H; Geometry.Height: 0.6mm; PCBL.Component: CHP;RESC;1500;1700;150;400;700;950;600; PCBL.Process: F;N;50;50;200;100;200;250;350;-50;0; PCB DECAL: RESC0603N; GNUM: G11-R0603-R105-AAA
R9-R11 R13 = RESC0603: Resistor, 49.9 OHM 1/10W 1% 0603 Thick; Manufacturer #1: Generic; Part Number: ERJ-3EKF49R9V; Description: Resistor,Chip;1.60mm L X 0.83mm W X 0.60mm H; Geometry.Height: 0.6mm; PCBL.Component: CHP;RESC;1500;1700;150;400;700;950;600; PCBL.Process: F;N;50;50;200;100;200;250;350;-50;0; Tolerance: 5%; PCB DECAL: RESC0603N; GNUM: G11-R0603-49R9-ABA
R14 R15 R35 R36 = CRCW040233R0JNED: as R43 on sheet Pg3_MICROCONTROLLER
R23 R24 R48 = RESC0402: as R4 on sheet Pg3_MICROCONTROLLER
R26 R27 R29 R34 = RESC0603: Resistor, 75 Ohm, 1/10W, 1%, SMD, Thick; Manufacturer #1: Generic; Part Number: ERJ-3EKF75R0V; PCB DECAL: RESC0603N; GNUM: G11-R0603-R750-ABA; Description: Resistor,Chip;1.60mm L X 0.83mm W X 0.60mm H; Geometry.Height: 0.6mm; PCBL.Component: CHP;RESC;1500;1700;150;400;700;950;600; PCBL.Process: F;N;50;50;200;100;200;250;350;-50;0
R28 = RESC1206: RES 1M OHM 5% 1206 TF; Manufacturer #1: IPC SM-782; Part Number: ERJ-8GEYJ105V; Description: SURFACE MOUNT RESISTOR OR CAPACITOR 0.062 X 0.126 INCHES; GNUM: G11-R1206-R105-CAA
R41 = RESC0603: Resistor, 4.87K Ohm, 1/10W, 1%, SMD, Thick; Manufacturer #1: Generic; Part Number: ERJ-3EKF4871V; Description: Resistor,Chip;1.60mm L X 0.83mm W X 0.60mm H; Geometry.Height: 0.6mm; PCBL.Component: CHP;RESC;1500;1700;150;400;700;950;600; PCBL.Process: F;N;50;50;200;100;200;250;350;-50;0; PCB DECAL: RESC0603N; GNUM: G11-R0603-4871-ABA
R42 = RESC0603: Resistor, 10K OHM 1/10W 5% 0603 SMD; Manufacturer #1: Generic; Part Number: ERJ-3GEYJ103V; PCB DECAL: RESC0603N; GNUM: G11-R0603-R103-AAA; Description: Resistor,Chip;1.60mm L X 0.83mm W X 0.60mm H; Geometry.Height: 0.6mm; PCBL.Component: CHP;RESC;1500;1700;150;400;700;950;600; PCBL.Process: F;N;50;50;200;100;200;250;350;-50;0
R44 = RESC0402: as R33 on sheet Pg3_MICROCONTROLLER
R50 = RESC0603: Resistor, 330 OHM 1/10W 5% 0603 SMD; Manufacturer #1: Generic; Part Number: ERJ-3GEYJ331V; PCB DECAL: RESC0603N; GNUM: G11-R0603-R331-AAA; Description: Resistor,Chip;1.60mm L X 0.83mm W X 0.60mm H; Geometry.Height: 0.6mm; PCBL.Component: CHP;RESC;1500;1700;150;400;700;950;600; PCBL.Process: F;N;50;50;200;100;200;250;350;-50;0
R53 R55 = RESC0603: Resistor, 330 OHM 1/10W 5% 0603 SMD; Manufacturer #1: Generic; Part Number: ERJ-3GEYJ331V; Description: Resistor,Chip;1.60mm L X 0.83mm W X 0.60mm H; Geometry.Height: 0.6mm; PCBL.Component: CHP;RESC;1500;1700;150;400;700;950;600; PCBL.Process: F;N;50;50;200;100;200;250;350;-50;0; PCB DECAL: RESC0603N; GNUM: G11-R0603-R331-AAA
T1 = HX1198FNL: TRANSFORMER, MDL, XFMR SGL ETHR LAN, SOIC-16; Manufacturer: PULSE ELECTRONICS; SymbolCreator: x0199378
TP19 TP20 = TP-040_RND: Test Point 40mil pad 20mil drill; Manufacturer: STD; Description: Test Point, O.040 Hole; Value: STD
U2 = TM4C129X: as U2 on sheet Pg3_MICROCONTROLLER
U3 = TPS2051B: Load Switch, 5.5V, SOT23-5, TPS2051BDBV; GNUM: G41-SOT23-2051-AAA

## Sheet Pg5_CAN_RS485.SchDoc: CAN RS485
size 431 x 279 mm; Date: Not shown in title block; ApprovedBy: Not shown in title block; CheckedBy: Not shown in title block; Author: Not shown in title block; CompanyName: Not shown in title block; Engineer: Not shown in title block; Organization: Not shown in title block; Address1: Not shown in title block; Address2: Not shown in title block; Address3: Not shown in title block; Address4: Not shown in title block; DocumentNumber: 5; Revision: Use project parameter SCH_Rev; SheetNumber: 5; SheetTotal: 9; PageSetup: Record=PageOptions|CenterHorizontal=True|CenterVertical=True|PrintScale=1.00|XCorrection=1.00|YCorrection=1.00|PrintKind=0|BorderSize=5000000|LeftOffset=0|BottomOffset=0|Orientation=2|PaperLength=1000|PaperWidth=1000|Scale=100|PaperSource=15|PrintQuality=600|MediaType=1|DitherType=10|PaperKind=Letter|PrintScaleMode=1
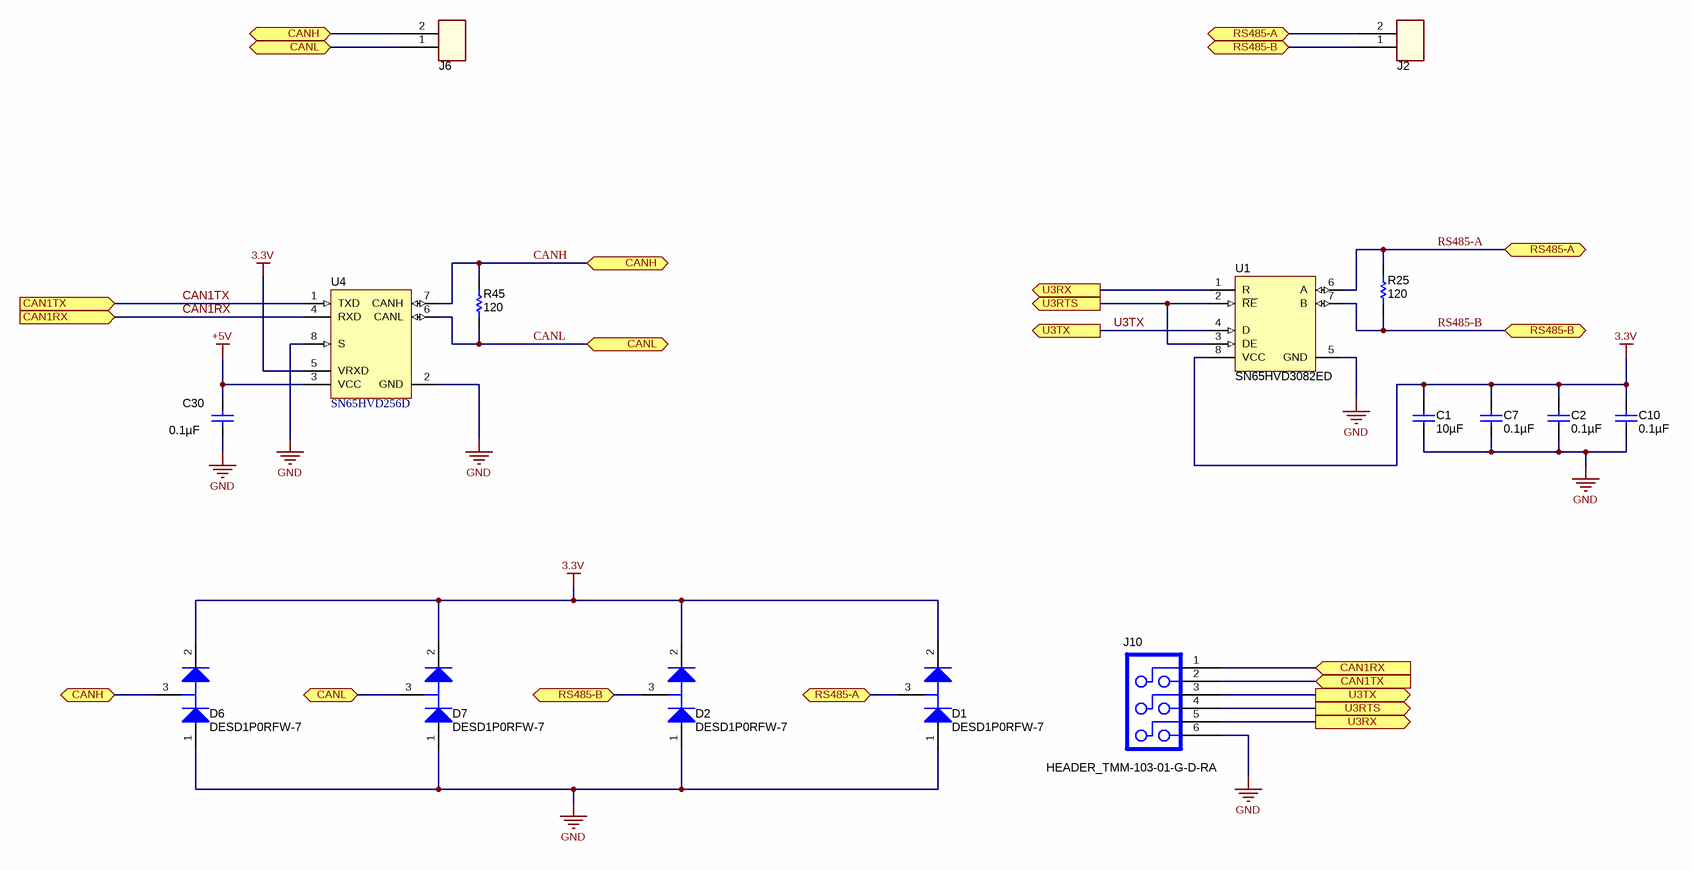
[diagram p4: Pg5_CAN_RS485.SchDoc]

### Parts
C1  ValueDisplayed: 10µF  [0603]  (hidden comment: C0603C106M9PACTU)
C2  ValueDisplayed: 0.1µF  [0603]  (hidden comment: GRM188R61C104KA01D)
C7  ValueDisplayed: 0.1µF  [0603]  (hidden comment: GRM188R61C104KA01D)
C10  ValueDisplayed: 0.1µF  [0603]  (hidden comment: GRM188R61C104KA01D)
C30  ValueDisplayed: 0.1µF  [0603]  (hidden comment: 06033C104JAT2A)
D1  DESD1P0RFW-7  [SOT-323]
D2  DESD1P0RFW-7  [SOT-323]
D6  DESD1P0RFW-7  [SOT-323]
D7  DESD1P0RFW-7  [SOT-323]
J2  CON-OSTVN02A150  [CN2_MTB_P100_PD80_D1.1_S5.54X6.5_STACK]  (value not drawn)
J6  CON-OSTVN02A150  [CN2_MTB_P100_PD80_D1.1_S5.54X6.5_STACK]  (value not drawn)
J10  HEADER_TMM-103-01-G-D-RA  [HEADER_TMM-103[2X]]
R25  value 120  [1206]  (hidden comment: RC1206FR-07120RL)
R45  value 120  [1206]  (hidden comment: RC1206FR-07120RL)
U1  SN65HVD3082ED  [D0008A_N]
U4  SN65HVD256D  [D0008A_L]

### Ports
CAN1RX (in), CAN1TX (in), CANH, CANL, RS485-A, RS485-B, U3RTS (out), U3RX (out), U3TX (out)

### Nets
3.3V: C1.1 C2.1 C7.1 C10.1 D1.2(K) D2.2(K) D6.2(K) D7.2(K) U1.8(VCC) U4.5(VRXD)
+5V: C30.2 U4.3(VCC)
GND: C1.2 C2.2 C7.2 C10.2 C30.1 D1.1(A) D2.1(A) D6.1(A) D7.1(A) J10.6 U1.5(GND) U4.2(GND) U4.8(S)  [project net GNDX]
CAN1RX: J10.1 U4.4(RXD) ; port CAN1RX
CAN1TX: J10.2 U4.1(TXD) ; port CAN1TX
CANH: D6.3(C) J6.2 R45.2 U4.7(CANH) ; port CANH
CANL: D7.3(C) J6.1 R45.1 U4.6(CANL) ; port CANL
RS485-A: D1.3(C) J2.2 R25.2 U1.6(A) ; port RS485-A
RS485-B: D2.3(C) J2.1 R25.1 U1.7(B) ; port RS485-B
U3RTS: J10.4 U1.2(~{RE}) U1.3(DE) ; port U3RTS
U3RX: J10.5 U1.1(R) ; port U3RX
U3TX: J10.3 U1.4(D) ; port U3TX

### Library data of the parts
C1 = C0603C106M9PACTU: CAP, CERM, 10uF, 6.3V, +/-20%, X5R, 0603; Manufacturer: Kemet; Polarized: N; CompType: Capacitor; U/M: EA; Cap_F: 0.00001; Tolerance_%: 20; ESR_Ohm: 0.004; Value1: 0.004 ohm; VDC_V: 6.3; IRMS_A: 8.9; TaMin_C: -55; TaMax_C: 85
C2 C7 C10 = GRM188R61C104KA01D: CAP, CERM, 0.1uF, 16V, +/-10%, X5R, 0603; Manufacturer: MuRata; Polarized: N; CompType: Capacitor; U/M: EA; Cap_F: 0.0000001; Tolerance_%: 10; Value1: Unknown; VDC_V: 16; TaMin_C: -55; TaMax_C: 85
C30 = 06033C104JAT2A: CAP, CERM, 0.1uF, 25V, +/-5%, X7R, 0603; Manufacturer: AVX; Polarized: N; CompType: Capacitor; U/M: EA; Cap_F: 0.0000001; Tolerance_%: 5; ESR_Ohm: 0.05; Value1: 0.05 ohm; VDC_V: 25; TaMin_C: -55; TaMax_C: 125
D1 D2 D6 D7 = BAV99WT1G: Diode, P-N, 70V, 0.2A, SOT-323; Manufacturer: Diodes Inc
J2 J6 = CON-OSTVN02A150: Terminal Block, 4x1, 2.54mm, TH; Manufacturer: On Shore Technology Inc; SymbolCreator: x0120606
J10 = HEADER_TMM-103-01-G-D-RA: Header, 2mm, Low Profile 2x3; Manufacturer: Samtec; Area: 57.75 mm
R25 R45 = RC1206FR-07120RL: RES, 120 ohm, 1%, 0.25W, 1206; Manufacturer: Yageo America; CompType: Resistor; Value_Code: 120R; Tolerance_%: 1; Power_W: 0.25; VDC_V: 200; TempCo: 100 ppm/C; U/M: EA
U1 = SN65HVD3082ED: IC, RS485 TRANSCEIVER LP, 8-SOIC; Manufacturer: TEXAS INSTRUMENTS; CompType: LOW-POWER RS-485 TRANSCEIVER; SymbolCreator: x0199378
U4 = SN65HVD256D: CAN Transceiver with Fast Loop Times for Highly Loaded Networks, 85 mA, 5 V, -40 to 125 degC, 8-pin SOIC (D), Green (RoHS & no Sb/Br); Manufacturer: Texas Instruments; Alternate Manufacturer: None; Alternate PartNumber: Equivalent; Drivers Per Package: 1; Bus Fault Voltage(V): -27 to 40; ICC(Max)(mA): 85; Supply Voltage(s)(V): 5; Rating: Catalog

## Sheet Pg6_MII_RMII_INTERFACE.SchDoc: MII / RMII INTERFACE
size 431 x 279 mm; Date: Not shown in title block; ApprovedBy: Not shown in title block; CheckedBy: Not shown in title block; Author: Not shown in title block; CompanyName: Not shown in title block; Engineer: Not shown in title block; Organization: Not shown in title block; Address1: Not shown in title block; Address2: Not shown in title block; Address3: Not shown in title block; Address4: Not shown in title block; DocumentNumber: 6; Revision: Use project parameter SCH_Rev; SheetNumber: 6; SheetTotal: 9; PageSetup: Record=PageOptions|CenterHorizontal=True|CenterVertical=True|PrintScale=1.00|XCorrection=1.00|YCorrection=1.00|PrintKind=0|BorderSize=5000000|LeftOffset=0|BottomOffset=0|Orientation=2|PaperLength=1000|PaperWidth=1000|Scale=100|PaperSource=15|PrintQuality=600|MediaType=1|DitherType=10|PaperKind=Letter|PrintScaleMode=1
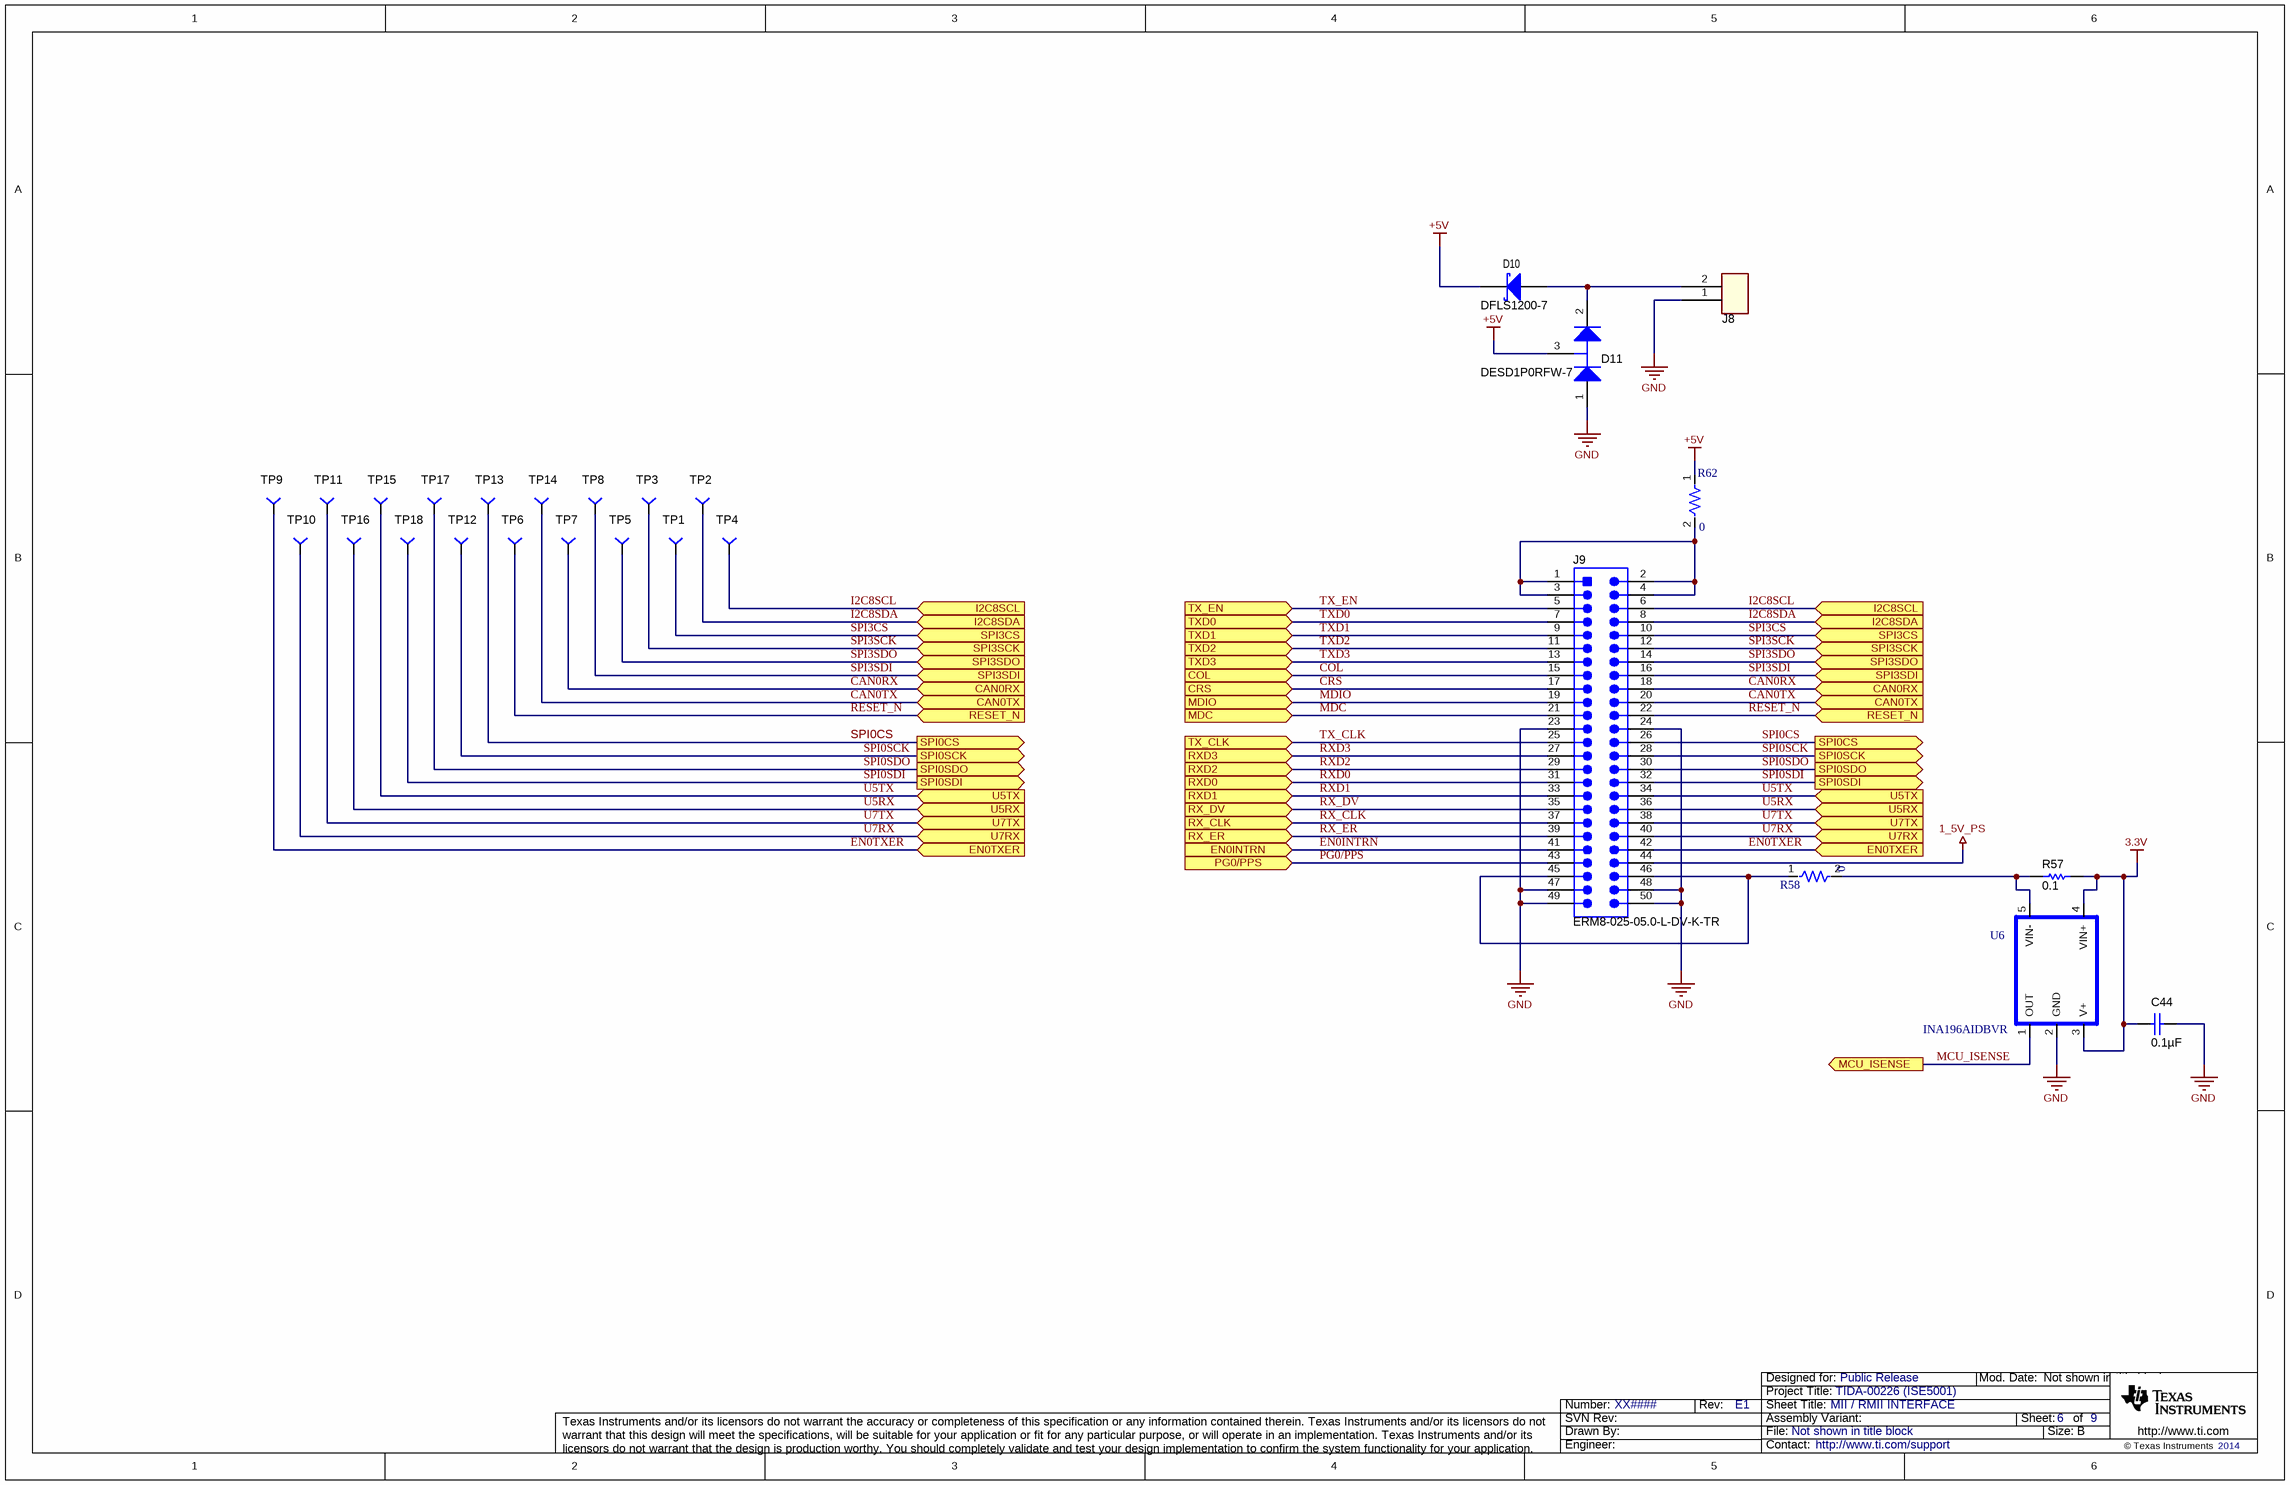
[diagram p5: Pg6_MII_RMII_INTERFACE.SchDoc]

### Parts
C44  ValueDisplayed: 0.1µF  [0603]  (hidden comment: 06033C104JAT2A)
D10  DFLS1200-7  [powerDI123]
D11  DESD1P0RFW-7  [SOT-323]
J8  CON-OSTVN02A150  [CN2_MTB_P100_PD80_D1.1_S5.54X6.5_STACK]  (value not drawn)
J9  ERM8-025-05.0-L-DV-K-TR  [SAMTEC_ERM8-025-05_0-L-DV-K-TR]
R57  value 0.1  [0603]  (hidden comment: ERJ-3RSFR10V)
R58  value 0  [0603]  (hidden comment: RESC0603)
R62  value 0  [0603]  (hidden comment: RESC0603)
TP1  TP1_PD40_D0.5_S50  [TP1_PD40_D0.5_S50]  (value not drawn)
TP2  TP1_PD40_D0.5_S50  [TP1_PD40_D0.5_S50]  (value not drawn)
TP3  TP1_PD40_D0.5_S50  [TP1_PD40_D0.5_S50]  (value not drawn)
TP4  TP1_PD40_D0.5_S50  [TP1_PD40_D0.5_S50]  (value not drawn)
TP5  TP1_PD40_D0.5_S50  [TP1_PD40_D0.5_S50]  (value not drawn)
TP6  TP1_PD40_D0.5_S50  [TP1_PD40_D0.5_S50]  (value not drawn)
TP7  TP1_PD40_D0.5_S50  [TP1_PD40_D0.5_S50]  (value not drawn)
TP8  TP1_PD40_D0.5_S50  [TP1_PD40_D0.5_S50]  (value not drawn)
TP9  TP1_PD40_D0.5_S50  [TP1_PD40_D0.5_S50]  (value not drawn)
TP10  TP1_PD40_D0.5_S50  [TP1_PD40_D0.5_S50]  (value not drawn)
TP11  TP1_PD40_D0.5_S50  [TP1_PD40_D0.5_S50]  (value not drawn)
TP12  TP1_PD40_D0.5_S50  [TP1_PD40_D0.5_S50]  (value not drawn)
TP13  TP1_PD40_D0.5_S50  [TP1_PD40_D0.5_S50]  (value not drawn)
TP14  TP1_PD40_D0.5_S50  [TP1_PD40_D0.5_S50]  (value not drawn)
TP15  TP1_PD40_D0.5_S50  [TP1_PD40_D0.5_S50]  (value not drawn)
TP16  TP1_PD40_D0.5_S50  [TP1_PD40_D0.5_S50]  (value not drawn)
TP17  TP1_PD40_D0.5_S50  [TP1_PD40_D0.5_S50]  (value not drawn)
TP18  TP1_PD40_D0.5_S50  [TP1_PD40_D0.5_S50]  (value not drawn)
U6  INA196AIDBVR  [SOT23-5P]

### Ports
CAN0RX, CAN0TX, COL, CRS, EN0INTRN, EN0TXER, I2C8SCL, I2C8SDA, MCU_ISENSE (out), MDC, MDIO, PG0/PPS, RESET_N, RX_CLK, RX_DV, RX_ER, RXD0, RXD1, RXD2, RXD3, SPI0CS, SPI0SCK, SPI0SDI, SPI0SDO, SPI3CS, SPI3SCK, SPI3SDI, SPI3SDO, TX_CLK, TX_EN, TXD0, TXD1, TXD2, TXD3, U5RX, U5TX, U7RX, U7TX

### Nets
1_5V_PS: J9.44
3.3V: C44.1 R57.2 U6.3(V+) U6.4(VIN+)
+5V: D10.1(K) D11.3(C) R62.1
GND: C44.2 D11.1(A) J8.1 J9.23 J9.24 J9.47 J9.48 J9.49 J9.50 U6.2(GND)  [project net GNDX]
CAN0RX: J9.18 TP7.1 ; port CAN0RX
CAN0TX: J9.20 TP14.1 ; port CAN0TX
COL: J9.15 ; port COL
CRS: J9.17 ; port CRS
EN0INTRN: J9.41 ; port EN0INTRN
EN0TXER: J9.42 TP9.1 ; port EN0TXER
I2C8SCL: J9.6 TP4.1 ; port I2C8SCL
I2C8SDA: J9.8 TP2.1 ; port I2C8SDA
MCU_ISENSE: U6.1(OUT) ; port MCU_ISENSE
MDC: J9.21 ; port MDC
MDIO: J9.19 ; port MDIO
PG0/PPS: J9.43 ; port PG0/PPS
RESET_N: J9.22 TP6.1 ; port RESET_N
RX_CLK: J9.37 ; port RX_CLK
RX_DV: J9.35 ; port RX_DV
RX_ER: J9.39 ; port RX_ER
RXD0: J9.31 ; port RXD0
RXD1: J9.33 ; port RXD1
RXD2: J9.29 ; port RXD2
RXD3: J9.27 ; port RXD3
SPI0CS: J9.26 TP13.1 ; port SPI0CS
SPI0SCK: J9.28 TP12.1 ; port SPI0SCK
SPI0SDI: J9.32 TP18.1 ; port SPI0SDI
SPI0SDO: J9.30 TP17.1 ; port SPI0SDO
SPI3CS: J9.10 TP1.1 ; port SPI3CS
SPI3SCK: J9.12 TP3.1 ; port SPI3SCK
SPI3SDI: J9.16 TP8.1 ; port SPI3SDI
SPI3SDO: J9.14 TP5.1 ; port SPI3SDO
TX_CLK: J9.25 ; port TX_CLK
TX_EN: J9.5 ; port TX_EN
TXD0: J9.7 ; port TXD0
TXD1: J9.9 ; port TXD1
TXD2: J9.11 ; port TXD2
TXD3: J9.13 ; port TXD3
U5RX: J9.36 TP16.1 ; port U5RX
U5TX: J9.34 TP15.1 ; port U5TX
U7RX: J9.40 TP10.1 ; port U7RX
U7TX: J9.38 TP11.1 ; port U7TX
NetD10_2: D10.2(A) D11.2(K) J8.2
NetJ9_1: J9.1 J9.2 J9.3 J9.4 R62.2
NetJ9_45: J9.45 J9.46 R58.1
NetR57_1: R57.1 R58.2 U6.5(VIN-)

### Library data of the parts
C44 = 06033C104JAT2A: as C30 on sheet Pg5_CAN_RS485
D10 = DFLS1200-7: Diode, Schottky, 200V, 1A, PowerDI123; Manufacturer: Diodes Inc.; U/M: EA; Vf_V: 0.85; Value2: 0.85V; Io_A: 1; Vr_V: 200; TJmax_C: 175; RJC_CperW: 7
D11 = BAV99WT1G: as D1 on sheet Pg5_CAN_RS485
J8 = CON-OSTVN02A150: as J2 on sheet Pg5_CAN_RS485
J9 = ERM8-025-05.0-L-DV-K-TR: CONN MICRO HS TERM STRP HDR 50 POS; Manufacturer: Samtec; SymbolCreator: a0799628; CompType: Header; U/M: EA
R57 = ERJ-3RSFR10V: RES, 0.1 ohm, 1%, 0.1W, 0603; Manufacturer: Panasonic; CompType: Resistor; Value_Code: R100; Tolerance_%: 1; TempCo: 300 ppm/C; EIA_Code: E96; U/M: EA
R58 R62 = RESC0603: Resistor, 0 OHM 1/10W 0603 SMD; Manufacturer #1: Generic; Part Number: ERJ-3GEY0R00V; PCB DECAL: RESC0603N; GNUM: G11-R0603-R000-AAA; Description: Resistor,Chip;1.60mm L X 0.83mm W X 0.60mm H; Geometry.Height: 0.6mm; PCBL.Component: CHP;RESC;1500;1700;150;400;700;950;600; PCBL.Process: F;N;50;50;200;100;200;250;350;-50;0; Tolerance: 5%
TP1-TP18 = TP-040_RND: as TP19 on sheet Pg4_10_100_ETHERNET_USB
U6 = INA19NAIDBV: IC, Current Shunt Monitor, -16V to 80V Common-Mode Range; Manufacturer: TI; Alternate Manufacturer: None; Area: 23200; Value: INA196/8AIDBV; PCB DECAL: REF3230AIDBVT

## Sheet Pg7_POWER_SUPPLY.SchDoc: POWER SUPPLY
size 431 x 279 mm; Date: Not shown in title block; ApprovedBy: Not shown in title block; CheckedBy: Not shown in title block; Author: Not shown in title block; CompanyName: Not shown in title block; Engineer: Not shown in title block; Organization: Not shown in title block; Address1: Not shown in title block; Address2: Not shown in title block; Address3: Not shown in title block; Address4: Not shown in title block; DocumentNumber: 7; Revision: Use project parameter SCH_Rev; SheetNumber: 7; SheetTotal: 9; PageSetup: Record=PageOptions|CenterHorizontal=True|CenterVertical=True|PrintScale=1.00|XCorrection=1.00|YCorrection=1.00|PrintKind=0|BorderSize=5000000|LeftOffset=0|BottomOffset=0|Orientation=2|PaperLength=1000|PaperWidth=1000|Scale=100|PaperSource=15|PrintQuality=600|MediaType=1|DitherType=10|PaperKind=Letter|PrintScaleMode=1
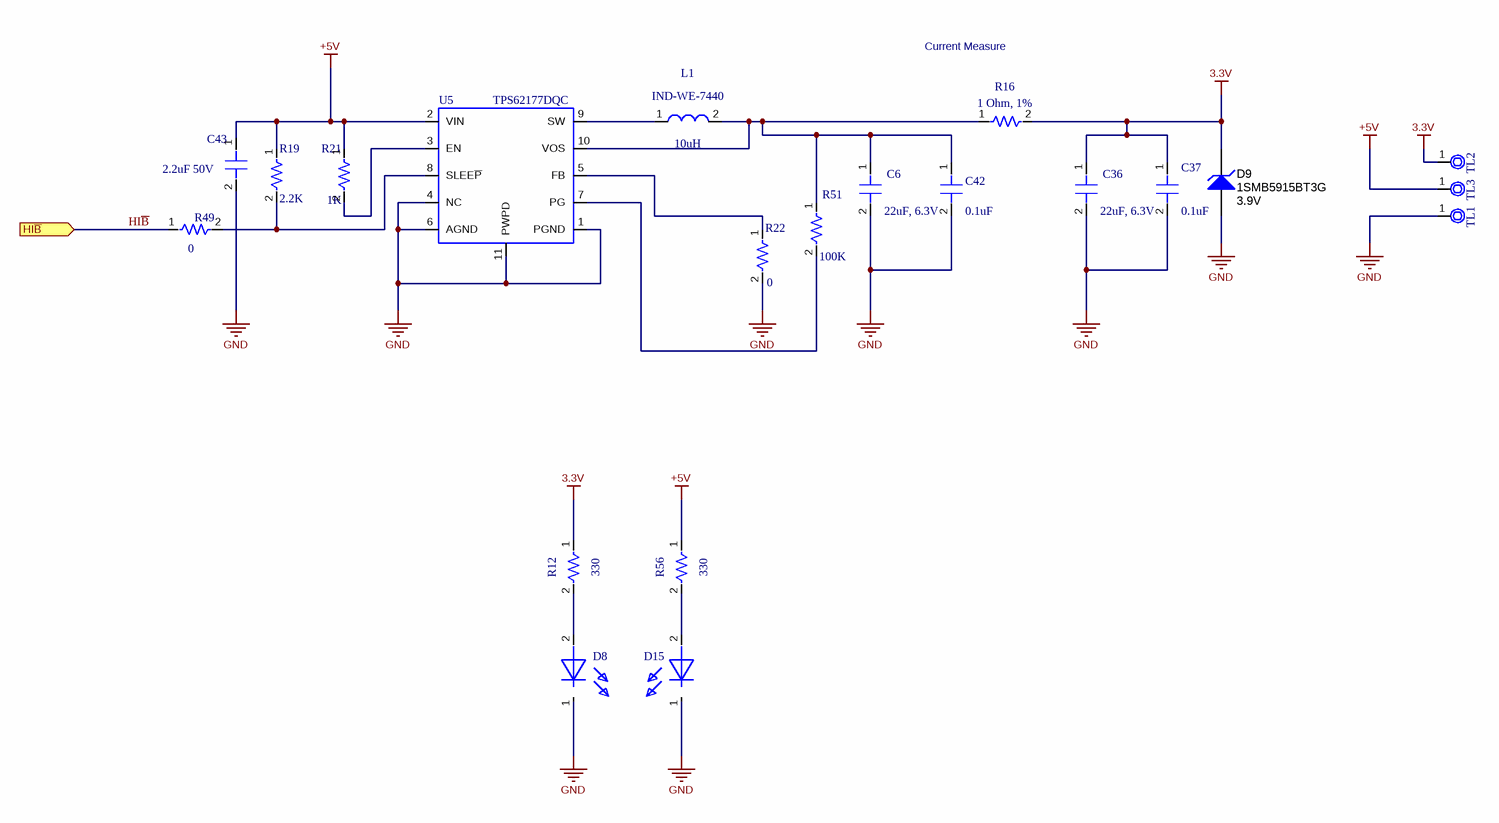
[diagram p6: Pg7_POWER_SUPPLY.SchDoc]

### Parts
C6  value 22uF, 6.3V  [0805]  (hidden comment: CAPC0805)
C36  value 22uF, 6.3V  [0805]  (hidden comment: CAPC0805)
C37  value 0.1uF  [0603]  (hidden comment: CAPC0603)
C42  value 0.1uF  [0603]  (hidden comment: CAPC0603)
C43  value 2.2uF 50V  [0805]  (hidden comment: CAPC0805)
D8  LED-0805  [DIOC0805N]  (value not drawn)
D9  1SMB5915BT3G  value 3.9V  [SMB]
D15  LED-0805  [DIOC0805N]  (value not drawn)
L1  IND-WE-7440  value 10uH  [IND_744029100]
R12  value 330  [0402]  (hidden comment: RESC0402)
R16  value 1 Ohm, 1%  [0603]  (hidden comment: RESC0603)
R19  value 2.2K  [0603]  (hidden comment: RESC0603)
R21  value 1K  [0603]  (hidden comment: RESC0603)
R22  value 0  [0603]  (hidden comment: RESC0603)
R49  value 0  [0603]  (hidden comment: RESC0603)
R51  value 100K  [0603]  (hidden comment: RESC0603)
R56  value 330  [0402]  (hidden comment: RESC0402)
TL1  TESTLOOP-100  [PAD70H39]  (value not drawn)
TL2  TESTLOOP-100  [PAD70H39]  (value not drawn)
TL3  TESTLOOP-100  [PAD70H39]  (value not drawn)
U5  TPS62177DQC  [DQC-10P]

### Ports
HI~{B}

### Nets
3.3V: C36.1 C37.1 D9.1(K) R12.1 R16.2 TL2.1
+5V: C43.1 R19.1 R21.1 R56.1 TL3.1 U5.2(VIN)
GND: C6.2 C36.2 C37.2 C42.2 C43.2 D8.1 D9.2(A) D15.1 R22.2 TL1.1 U5.1(PGND) U5.4(NC) U5.6(AGND) U5.11(PWPD)  [project net GNDX]
HI~{B}: R49.1 ; port HI~{B}
NetC6_1: C6.1 C42.1 L1.2 R16.1 R51.1 U5.10(VOS)
NetD8_2: D8.2 R12.2
NetD15_2: D15.2 R56.2
NetL1_1: L1.1 U5.9(SW)
NetR19_2: R19.2 R49.2 U5.8(SLEE~{P})
NetR21_2: R21.2 U5.3(EN)
NetR22_1: R22.1 U5.5(FB)
NetR51_2: R51.2 U5.7(PG)

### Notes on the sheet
- Current Measure

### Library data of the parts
C6 = CAPC0805: Capacitor, 22uF 6.3V 20% X5R 0805; PartNumber: C2012X5R0J226M; GNUM: G10-C0805-C226-DCB; Description: Capacitor,Chip;2.00mm L X 1.25mm W X 1.10mm H; Geometry.Height: 1.1mm; PCBL.Component: CHP;CAPC;1800;2200;250;750;1050;1450;1100; PCBL.Process: F;N;50;50;200;100;200;250;350;-50;0
C36 = CAPC0805: Capacitor, 22uF 6.3V 20% X5R 0805; PartNumber: C2012X5R0J226M/1.25; GNUM: G10-C0805-C226-DCB; Description: Capacitor,Chip;2.00mm L X 1.25mm W X 1.10mm H; Geometry.Height: 1.1mm; PCBL.Component: CHP;CAPC;1800;2200;250;750;1050;1450;1100; PCBL.Process: F;N;50;50;200;100;200;250;350;-50;0
C37 C42 = CAPC0603: as C5 on sheet Pg3_MICROCONTROLLER
C43 = CAPC0805: Capacitor, 2.2uF 50V 10% X5R 0805; Part Number: C2012X5R1H225K; GNUM: G10-C0805-C225-ABB
D8 = LED-0805: as D14 on sheet Pg4_10_100_ETHERNET_USB
D9 = 1SMB5915BT3G: Diode, Zener, 3.9V, 550mW, SMB; Manufacturer: ON Semiconductor; SymbolCreator: a0412235; U/M: EA; Power_W: 0.55; Vz_V: 3.9; Value1: 0.55W; RJA_CperW: 226
D15 = LED-0805: LED AMBER CLEAR 0805 SMD; Part Number: LTST-C170AKT; GNUM: G14-D0805-AMB0-AAA
L1 = IND-WE-7440: Inductor 10uH, SMD 2.8x2.8mm, 0.5A, 0.47 Ohm; Part Number: 744029100; GNUM: G12-SM2X2-I100-ADA; PCB DECAL: IND-WE-2M8
R12 R56 = RESC0402: Resistor, 330 ohm, 1/10W, 5%, 0402; Manufacturer #1: Generic; Part Number: RC0402FR-07330RL; Description: Resistor,Chip;1.00mm L X 0.5mm W X 0.35mm H; Geometry.Height: 0.35mm; PCBL.Component: CHP;RESC;1500;1700;150;400;700;950;600; PCBL.Process: F;N;50;50;200;100;200;250;350;-50;0; PCB DECAL: RESC0402N; GNUM: G11-R0402-3300-AAA
R16 = RESC0603: Resistor, 1 OHM 1/10W 1% 0603, Thick; Manufacturer #1: Generic; Part Number: ERJ-3RQF1R0V; PCB DECAL: RESC0603N; GNUM: G11-R0603-R010-ABA; Description: Resistor,Chip;1.60mm L X 0.83mm W X 0.60mm H; Geometry.Height: 0.6mm; PCBL.Component: CHP;RESC;1500;1700;150;400;700;950;600; PCBL.Process: F;N;50;50;200;100;200;250;350;-50;0; Tolerance: 5%
R19 = RESC0603: as R1 on sheet Pg3_MICROCONTROLLER
R21 = RESC0603: Resistor, 1K Ohm, 1/10W, 5%, SMD, Thick; Manufacturer #1: Generic; Part Number: ERJ-3GEYJ102V; PCB DECAL: RESC0603N; GNUM: G11-R0603-R102-AAA; Description: Resistor,Chip;1.60mm L X 0.83mm W X 0.60mm H; Geometry.Height: 0.6mm; PCBL.Component: CHP;RESC;1500;1700;150;400;700;950;600; PCBL.Process: F;N;50;50;200;100;200;250;350;-50;0
R22 R49 = RESC0603: as R58 on sheet Pg6_MII_RMII_INTERFACE
R51 = RESC0603: Resistor, 100K OHM 1/10W 5% 0603 Thick; Part Number: ERJ-3GEYJ104V; PCB DECAL: RESC0603N; GNUM: G11-R0603-R104-AAA
TL1-TL3 = TESTLOOP-100: Terminal, Test Point Miniature Loop, Red, T-Hole; Part Number: 5000; Manufacturer #1: Keystone Electronics; Description: Test loop, Miniature White, Through-hole; GNUM: G20-K5000-TP00-AAA
U5 = TPS62177DQC: Regulator, Step Down  3.3V, 0.5A; GNUM: G51-DQC10-2177-AAA

## Sheet Pg8_SPARE_AND_DEBUG.SchDoc: SPARE AND DEBUG
size 431 x 279 mm; Date: Not shown in title block; ApprovedBy: Not shown in title block; CheckedBy: Not shown in title block; Author: Not shown in title block; CompanyName: Not shown in title block; Engineer: Not shown in title block; Organization: Not shown in title block; Address1: Not shown in title block; Address2: Not shown in title block; Address3: Not shown in title block; Address4: Not shown in title block; DocumentNumber: 8; Revision: Use project parameter SCH_Rev; SheetNumber: 8; SheetTotal: 9; PageSetup: Record=PageOptions|CenterHorizontal=True|CenterVertical=True|PrintScale=1.00|XCorrection=1.00|YCorrection=1.00|PrintKind=0|BorderSize=5000000|LeftOffset=0|BottomOffset=0|Orientation=2|PaperLength=1000|PaperWidth=1000|Scale=100|PaperSource=15|PrintQuality=600|MediaType=1|DitherType=10|PaperKind=Letter|PrintScaleMode=1
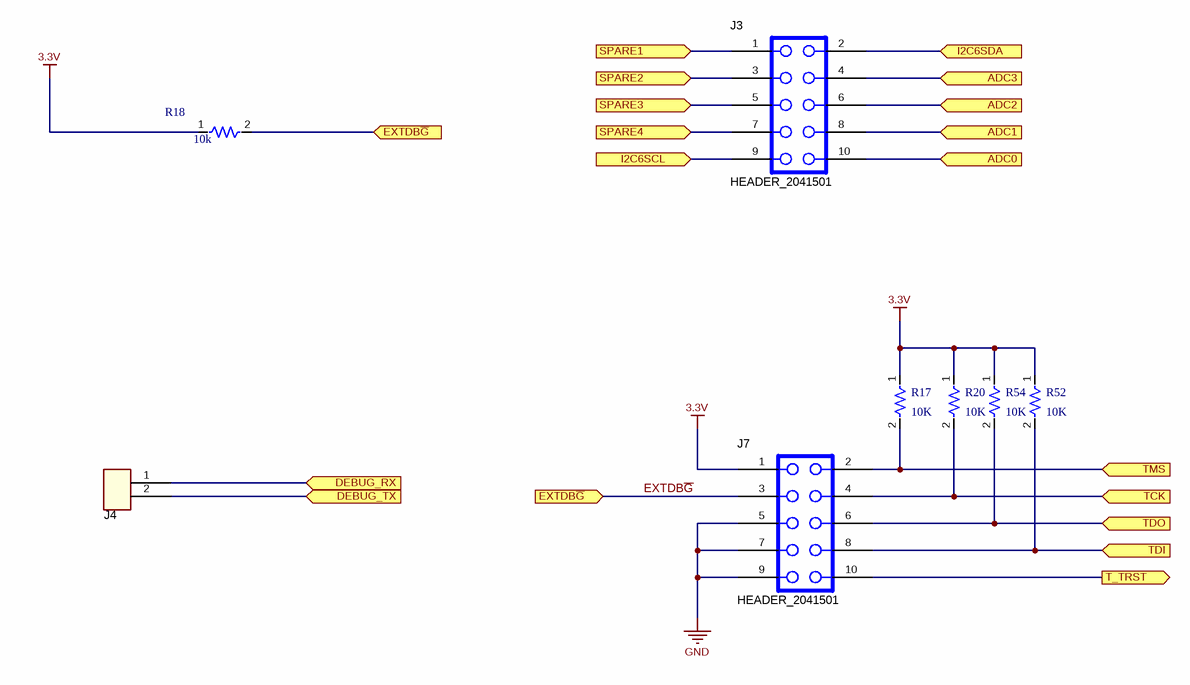
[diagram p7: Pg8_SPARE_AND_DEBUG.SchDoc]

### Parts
J3  HEADER_2041501  [HDR2X5 _2MM]
J4  CON-OSTVN02A150  [CN2_MTB_P100_PD80_D1.1_S5.54X6.5_STACK]  (value not drawn)
J7  HEADER_2041501  [HDR2X5 _2MM]
R17  value 10K  [0402]  (hidden comment: RESC0402)
R18  value 10k  [0402]  (hidden comment: RESC0402)
R20  value 10K  [0402]  (hidden comment: RESC0402)
R52  value 10K  [0402]  (hidden comment: RESC0402)
R54  value 10K  [0402]  (hidden comment: RESC0402)

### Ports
ADC0, ADC1, ADC2, ADC3, DEBUG_RX, DEBUG_TX, EXTDB~{G} (in), I2C6SCL, I2C6SDA, SPARE1, SPARE2, SPARE3, SPARE4, T_TRST, TCK, TDI, TDO, TMS

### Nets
3.3V: J7.1 R17.1 R18.1 R20.1 R52.1 R54.1
GND: J7.5 J7.7 J7.9  [project net GNDX]
EXTDB~{G}: J7.3 R18.2 ; port EXTDB~{G}
ADC0: J3.10 ; port ADC0
ADC1: J3.8 ; port ADC1
ADC2: J3.6 ; port ADC2
ADC3: J3.4 ; port ADC3
DEBUG_RX: J4.1 ; port DEBUG_RX
DEBUG_TX: J4.2 ; port DEBUG_TX
I2C6SCL: J3.9 ; port I2C6SCL
I2C6SDA: J3.2 ; port I2C6SDA
SPARE1: J3.1 ; port SPARE1
SPARE2: J3.3 ; port SPARE2
SPARE3: J3.5 ; port SPARE3
SPARE4: J3.7 ; port SPARE4
T_TRST: J7.10 ; port T_TRST
TCK: J7.4 R20.2 ; port TCK
TDI: J7.8 R52.2 ; port TDI
TDO: J7.6 R54.2 ; port TDO
TMS: J7.2 R17.2 ; port TMS

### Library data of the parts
J3 J7 = HEADER_2041501: Header, 2X5 2mm spacing; PartNumber: M22-2020505; Manufacturer: Harwin Inc; Area: 55 mm
J4 = CON-OSTVN02A150: as J2 on sheet Pg5_CAN_RS485
R17 R18 R20 R52 R54 = RESC0402: as R33 on sheet Pg3_MICROCONTROLLER

## Sheet Pg9_Hardware_ANSI-B.SchDoc: MOUNTING HOLES, FIDUCIALS MARKING
size 431 x 279 mm; Date: Not shown in title block; ApprovedBy: Not shown in title block; CheckedBy: Not shown in title block; Author: Not shown in title block; CompanyName: Not shown in title block; Engineer: Not shown in title block; Organization: Not shown in title block; Address1: Not shown in title block; Address2: Not shown in title block; Address3: Not shown in title block; Address4: Not shown in title block; DocumentNumber: 9; Revision: Use project parameter SCH_Rev; SheetNumber: 9; SheetTotal: 9; PageSetup: Record=PageOptions|CenterHorizontal=True|CenterVertical=True|PrintScale=1.00|XCorrection=1.00|YCorrection=1.00|PrintKind=0|BorderSize=5000000|LeftOffset=0|BottomOffset=0|Orientation=2|PaperLength=1000|PaperWidth=1000|Scale=100|PaperSource=15|PrintQuality=600|MediaType=1|DitherType=10|PaperKind=Letter|PrintScaleMode=1
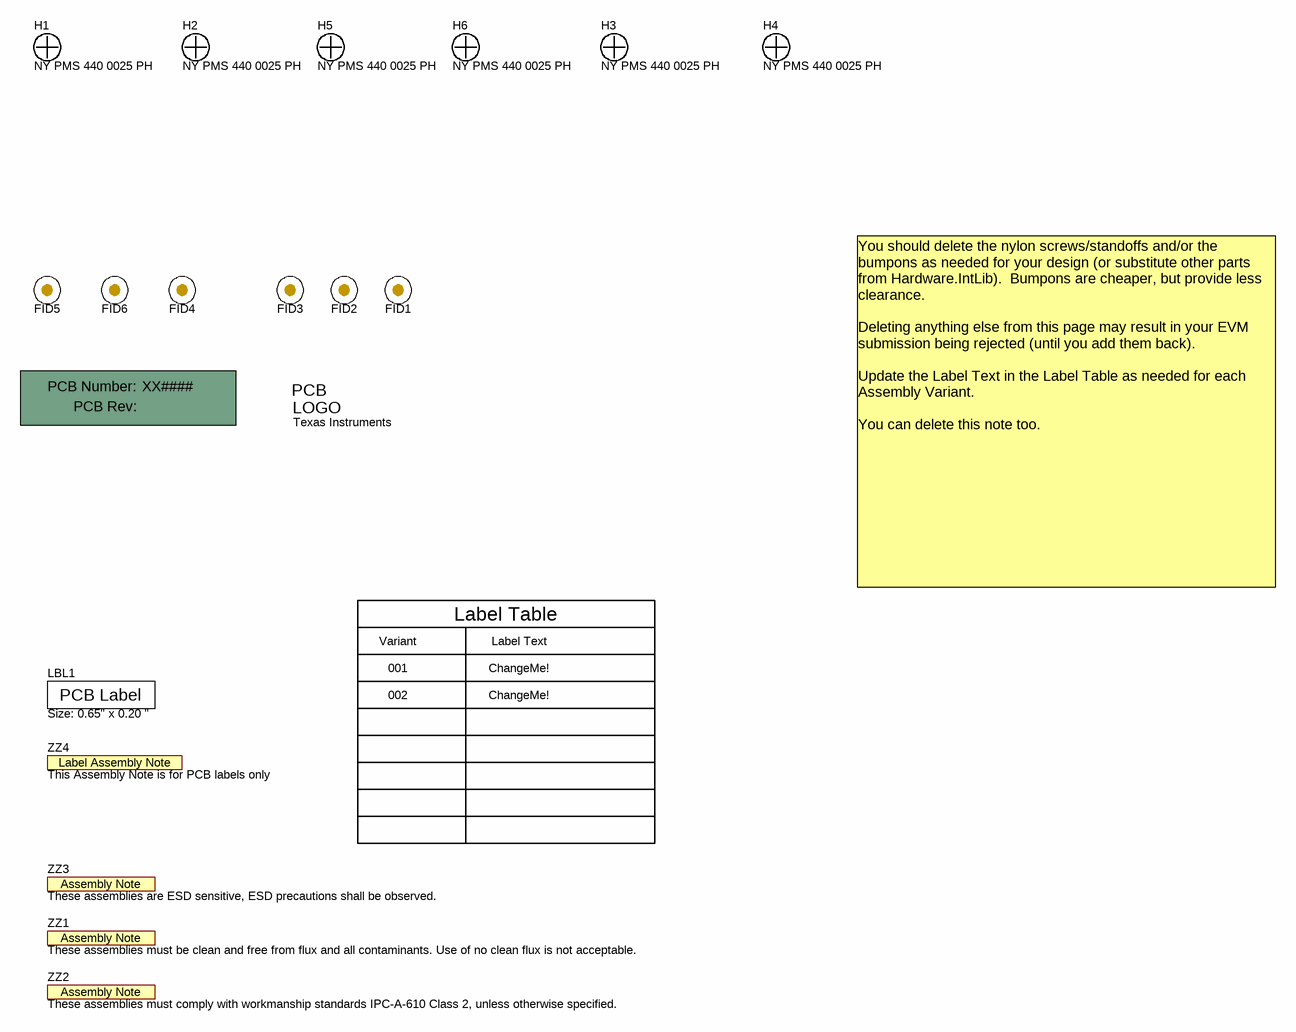
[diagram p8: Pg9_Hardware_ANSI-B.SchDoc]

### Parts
!PCB  Printed Circuit Board  (value not drawn)  (mechanical)
FID1  Fiducial  [Fiducial10-20]  (value not drawn)
FID2  Fiducial  [Fiducial10-20]  (value not drawn)
FID3  Fiducial  [Fiducial10-20]  (value not drawn)
FID4  Fiducial  [Fiducial10-20]  (value not drawn)
FID5  Fiducial  [Fiducial10-20]  (value not drawn)
FID6  Fiducial  [Fiducial10-20]  (value not drawn)
H1  NY PMS 440 0025 PH  [MH3.2_H5_W6_KO8_STARHEAD]
H2  NY PMS 440 0025 PH  [MH3.2_H5_W6_KO8_STARHEAD]
H3  NY PMS 440 0025 PH  [MH3.2_H5_W6_KO8_STARHEAD]
H4  NY PMS 440 0025 PH  [MH3.2_H5_W6_KO8_STARHEAD]
H5  NY PMS 440 0025 PH  [MH3.2_H5_W6_KO8_STARHEAD]
H6  NY PMS 440 0025 PH  [MH3.2_H5_W6_KO8_STARHEAD]
LBL1  Size: 0.65" x 0.20 "  [Label_650x200]
Logo1  Texas Instruments  [TI_Stacked_SolderMask_Small]  (no BOM)
ZZ1  These assemblies must be clean and free from flux and all contaminants. Use of no clean flux is not acceptable.  [AssemblyNote]  (no BOM)
ZZ2  These assemblies must comply with workmanship standards IPC-A-610 Class 2, unless otherwise specified.  [AssemblyNote]  (no BOM)
ZZ3  These assemblies are ESD sensitive, ESD precautions shall be observed.  [AssemblyNote]  (no BOM)
ZZ4  This Assembly Note is for PCB labels only  [AssemblyNoteLabel]  (no BOM)

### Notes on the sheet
- Variant
- Label Table
- Label Text
- You should delete the nylon screws/standoffs and/or the bumpons as needed for your design (or substitute other parts from Hardware.IntLib).  Bumpons are cheaper, but provide less clearance.
  Deleting anything else from this page may result in your EVM submission being rejected (until you add them back).
  Update the Label Text in the Label Table as needed for each Assembly Variant.
  You can delete this note too.
- 001
- 002
- ChangeMe!

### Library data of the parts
!PCB = PCB: Manufacturer: Any; PartNumber: XX####; SymbolCreator: a0412235
FID1-FID6 = Fiducial: Fiducial mark.  There is nothing to buy or mount.; SymbolCreator: codlsc
H1-H6 = NY PMS 440 0025 PH: Machine Screw, Round, #4-40 x 1/4, Nylon, Philips panhead; Manufacturer: B&F Fastener Supply; CompType: Hardware; SymbolCreator: codlsc; U/M: EA
LBL1 = THT-14-423-10: Thermal Transfer Printable Labels, 0.650" W x 0.200" H - 10,000 per roll; Manufacturer: Brady; SymbolCreator: a0412235; CompType: Label
Logo1 = TI_Logo: Texas Instrument Corporate Signature; SymbolCreator: codlsc
ZZ1-ZZ3 = AssemblyNote: SymbolCreator: codlsc
ZZ4 = AssemblyNoteLabel: SymbolCreator: a0412235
